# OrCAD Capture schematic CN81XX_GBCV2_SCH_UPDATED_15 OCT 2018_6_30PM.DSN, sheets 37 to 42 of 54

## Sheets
37 41.TIVA IO'S: size Custom; title: TIVA IO'S
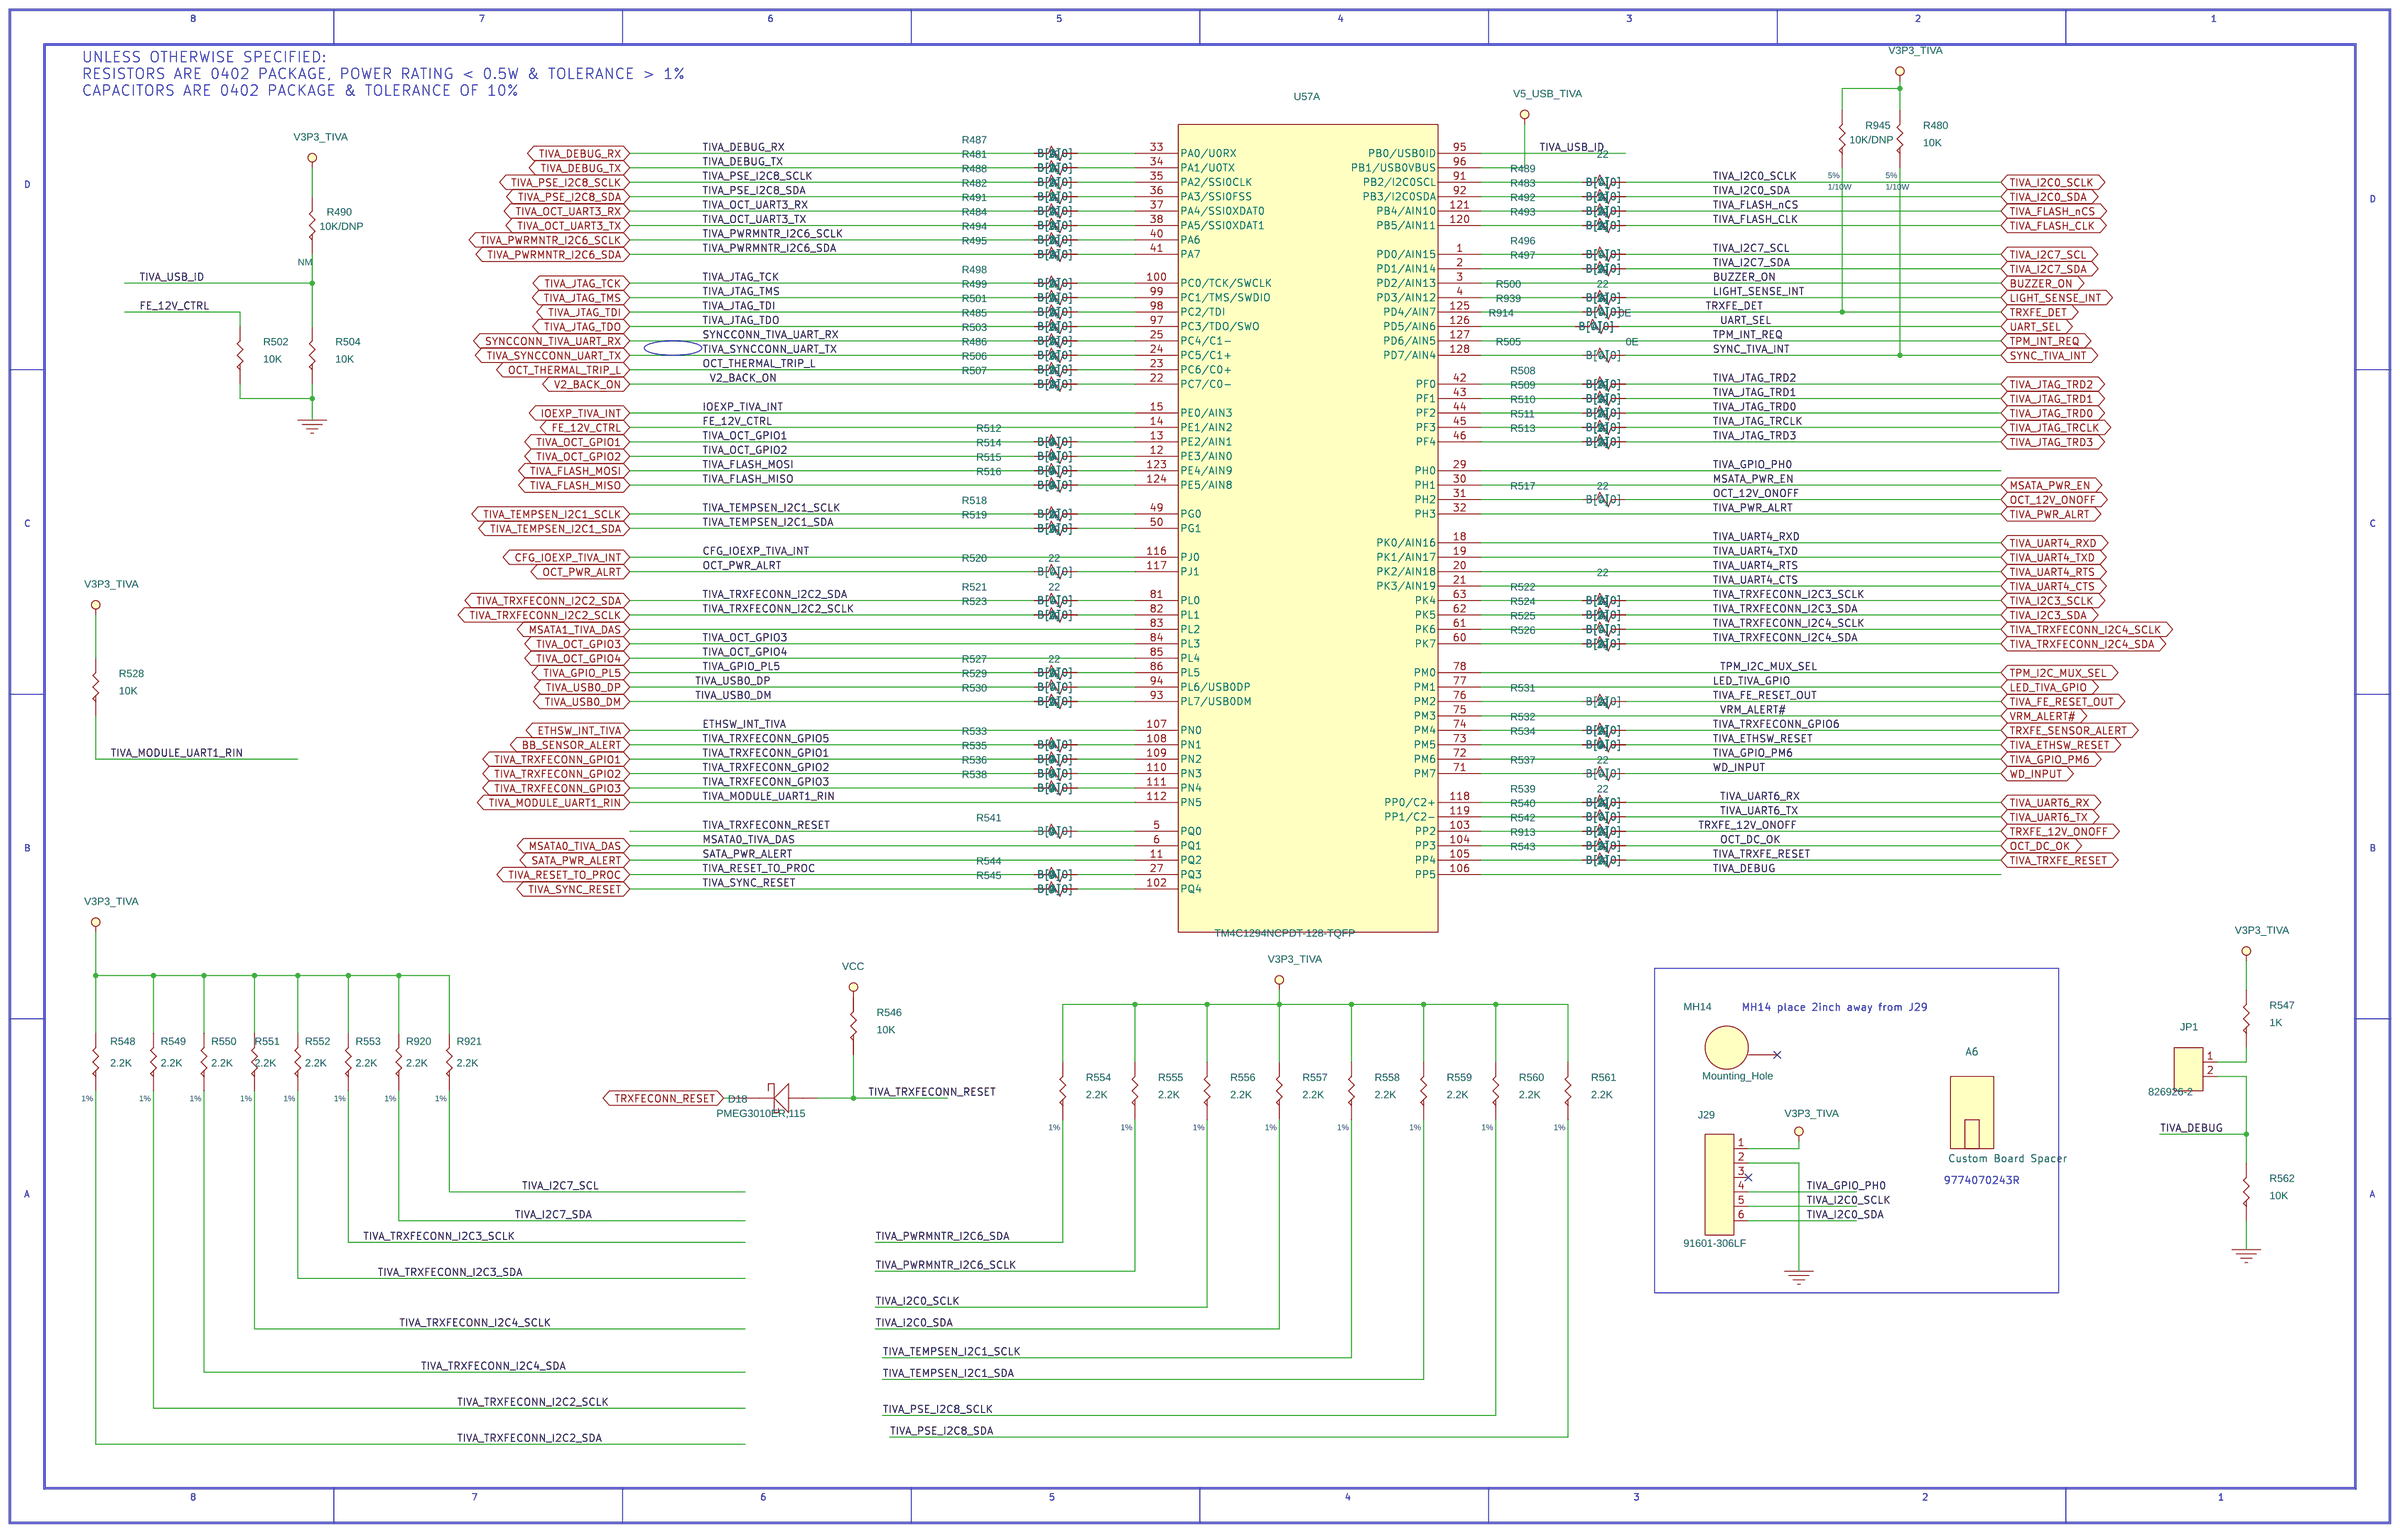
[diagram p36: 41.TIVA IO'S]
38 42.TIVA POWER: size Custom; title: TIVA POWER
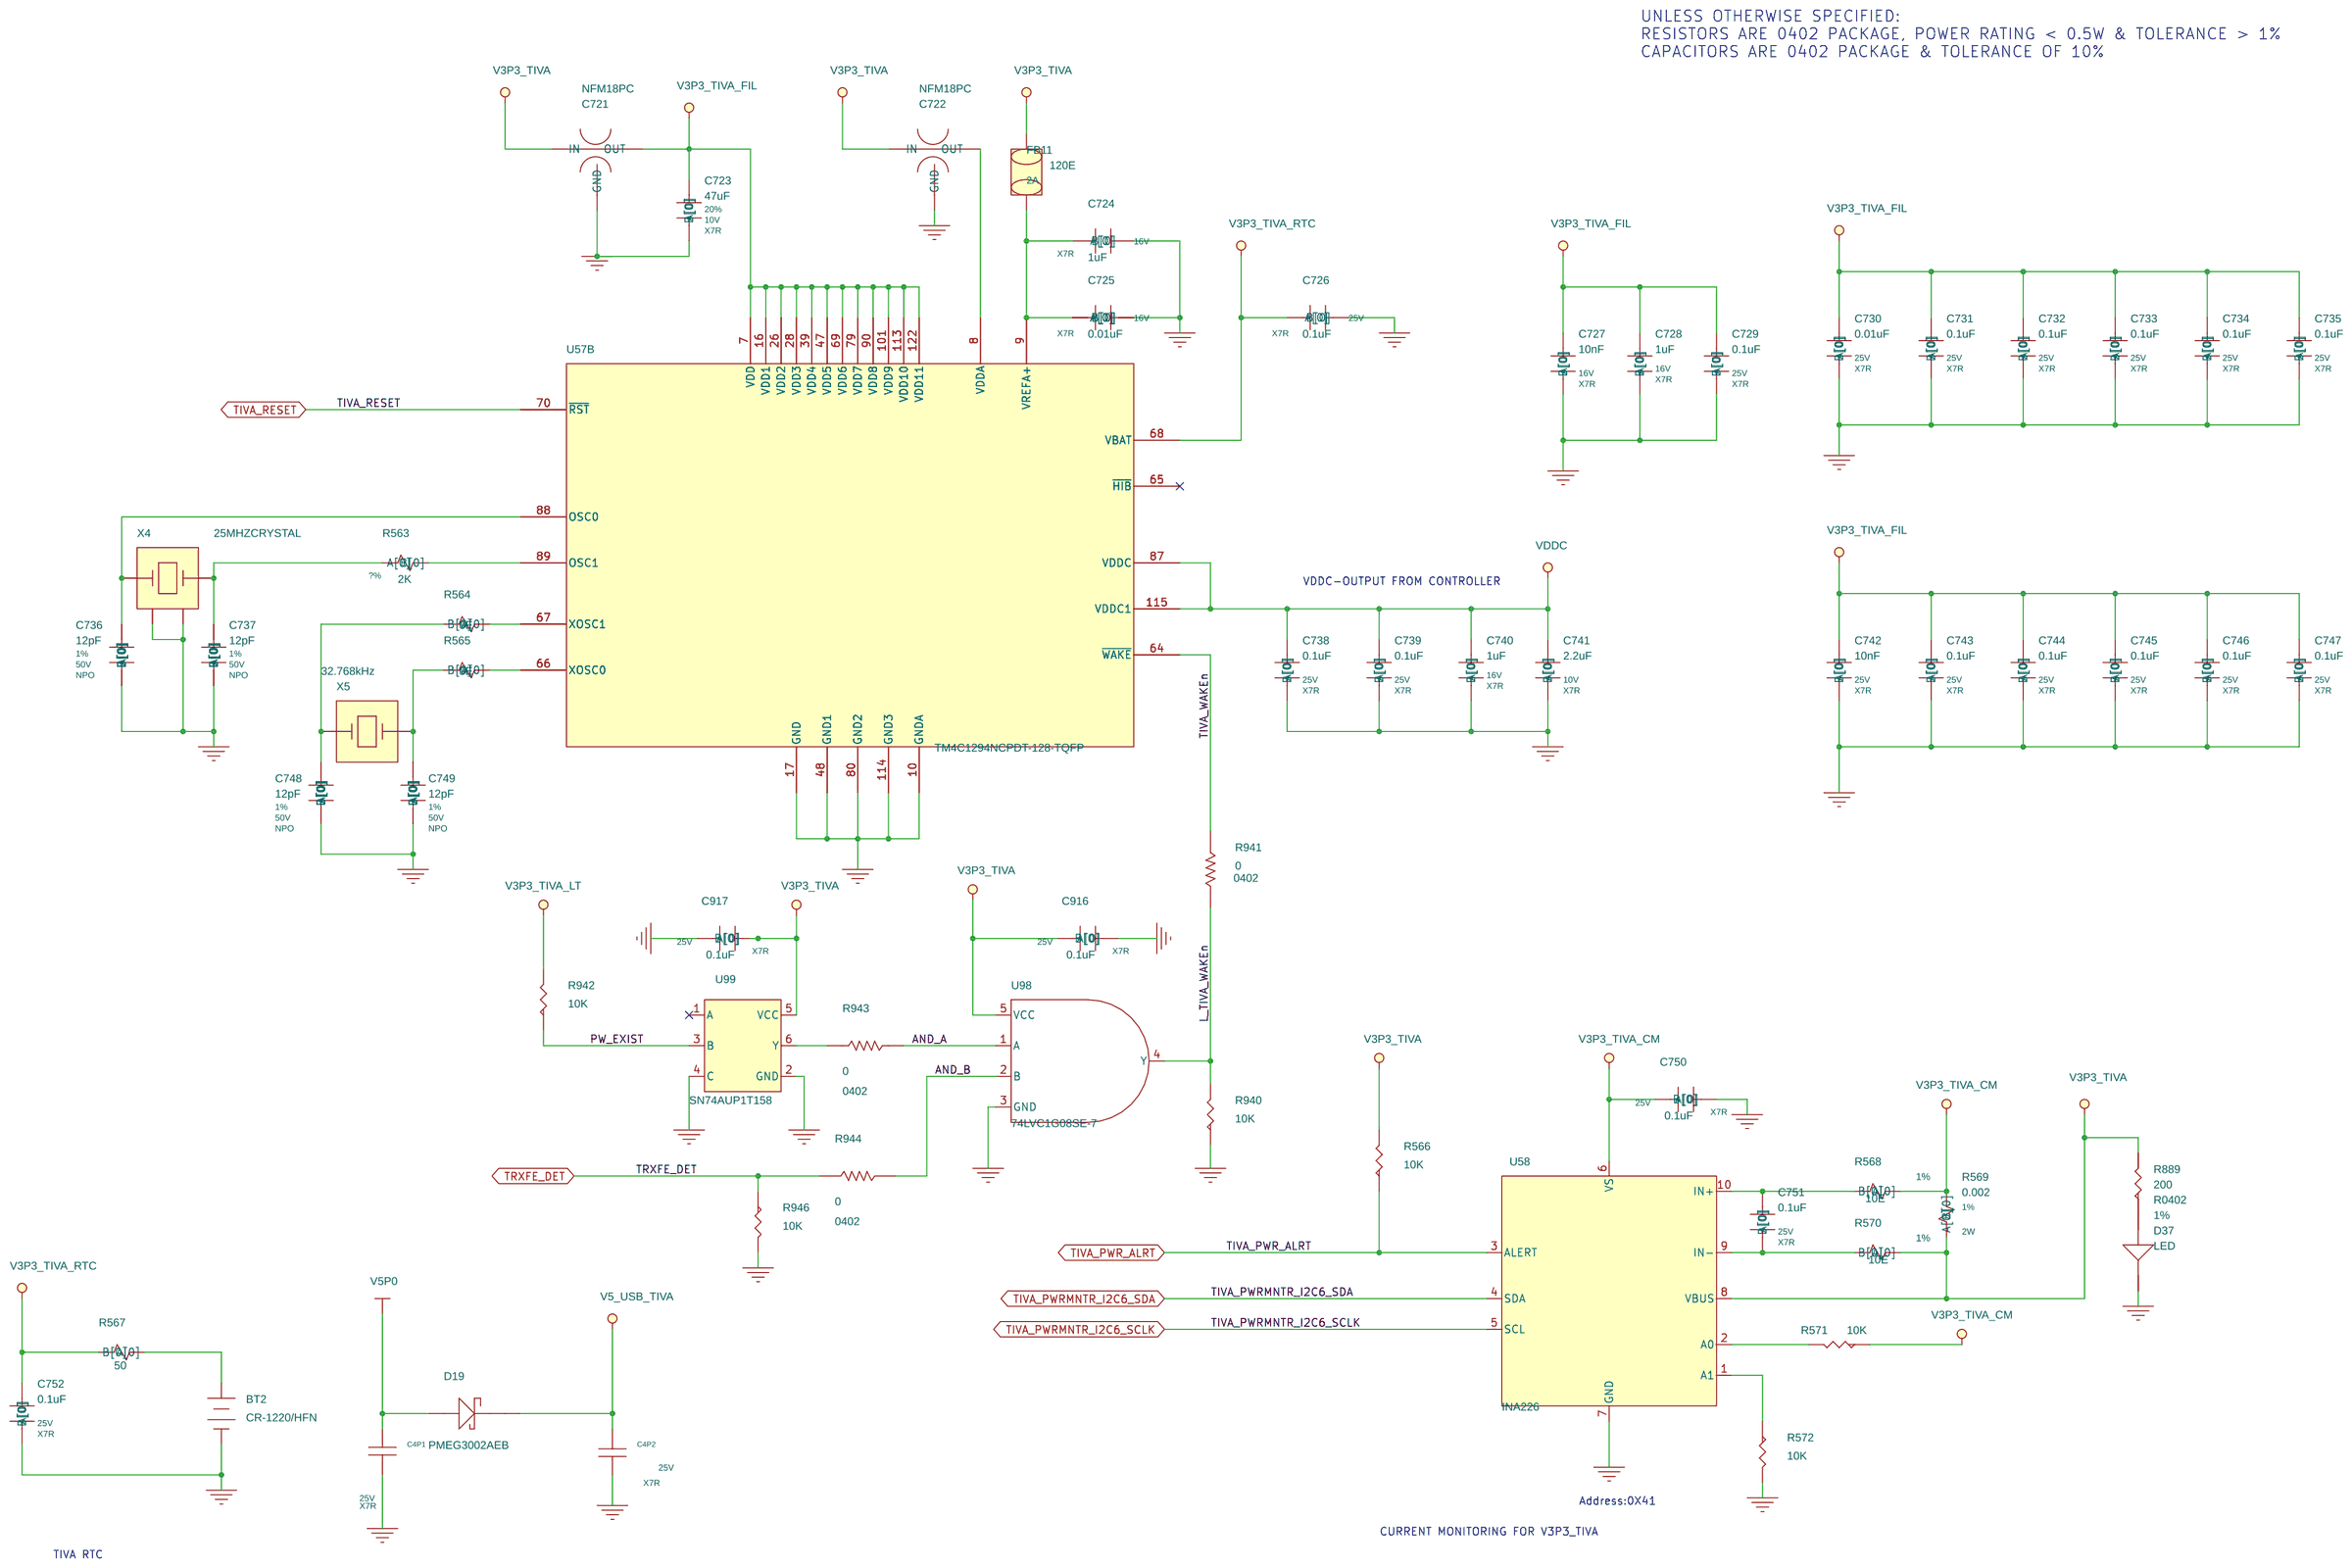
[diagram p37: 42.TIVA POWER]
39 43.TIVA JTAG CONNECTOR&ICD&LED: size B; title: TIVA JTAG CONNECTOR
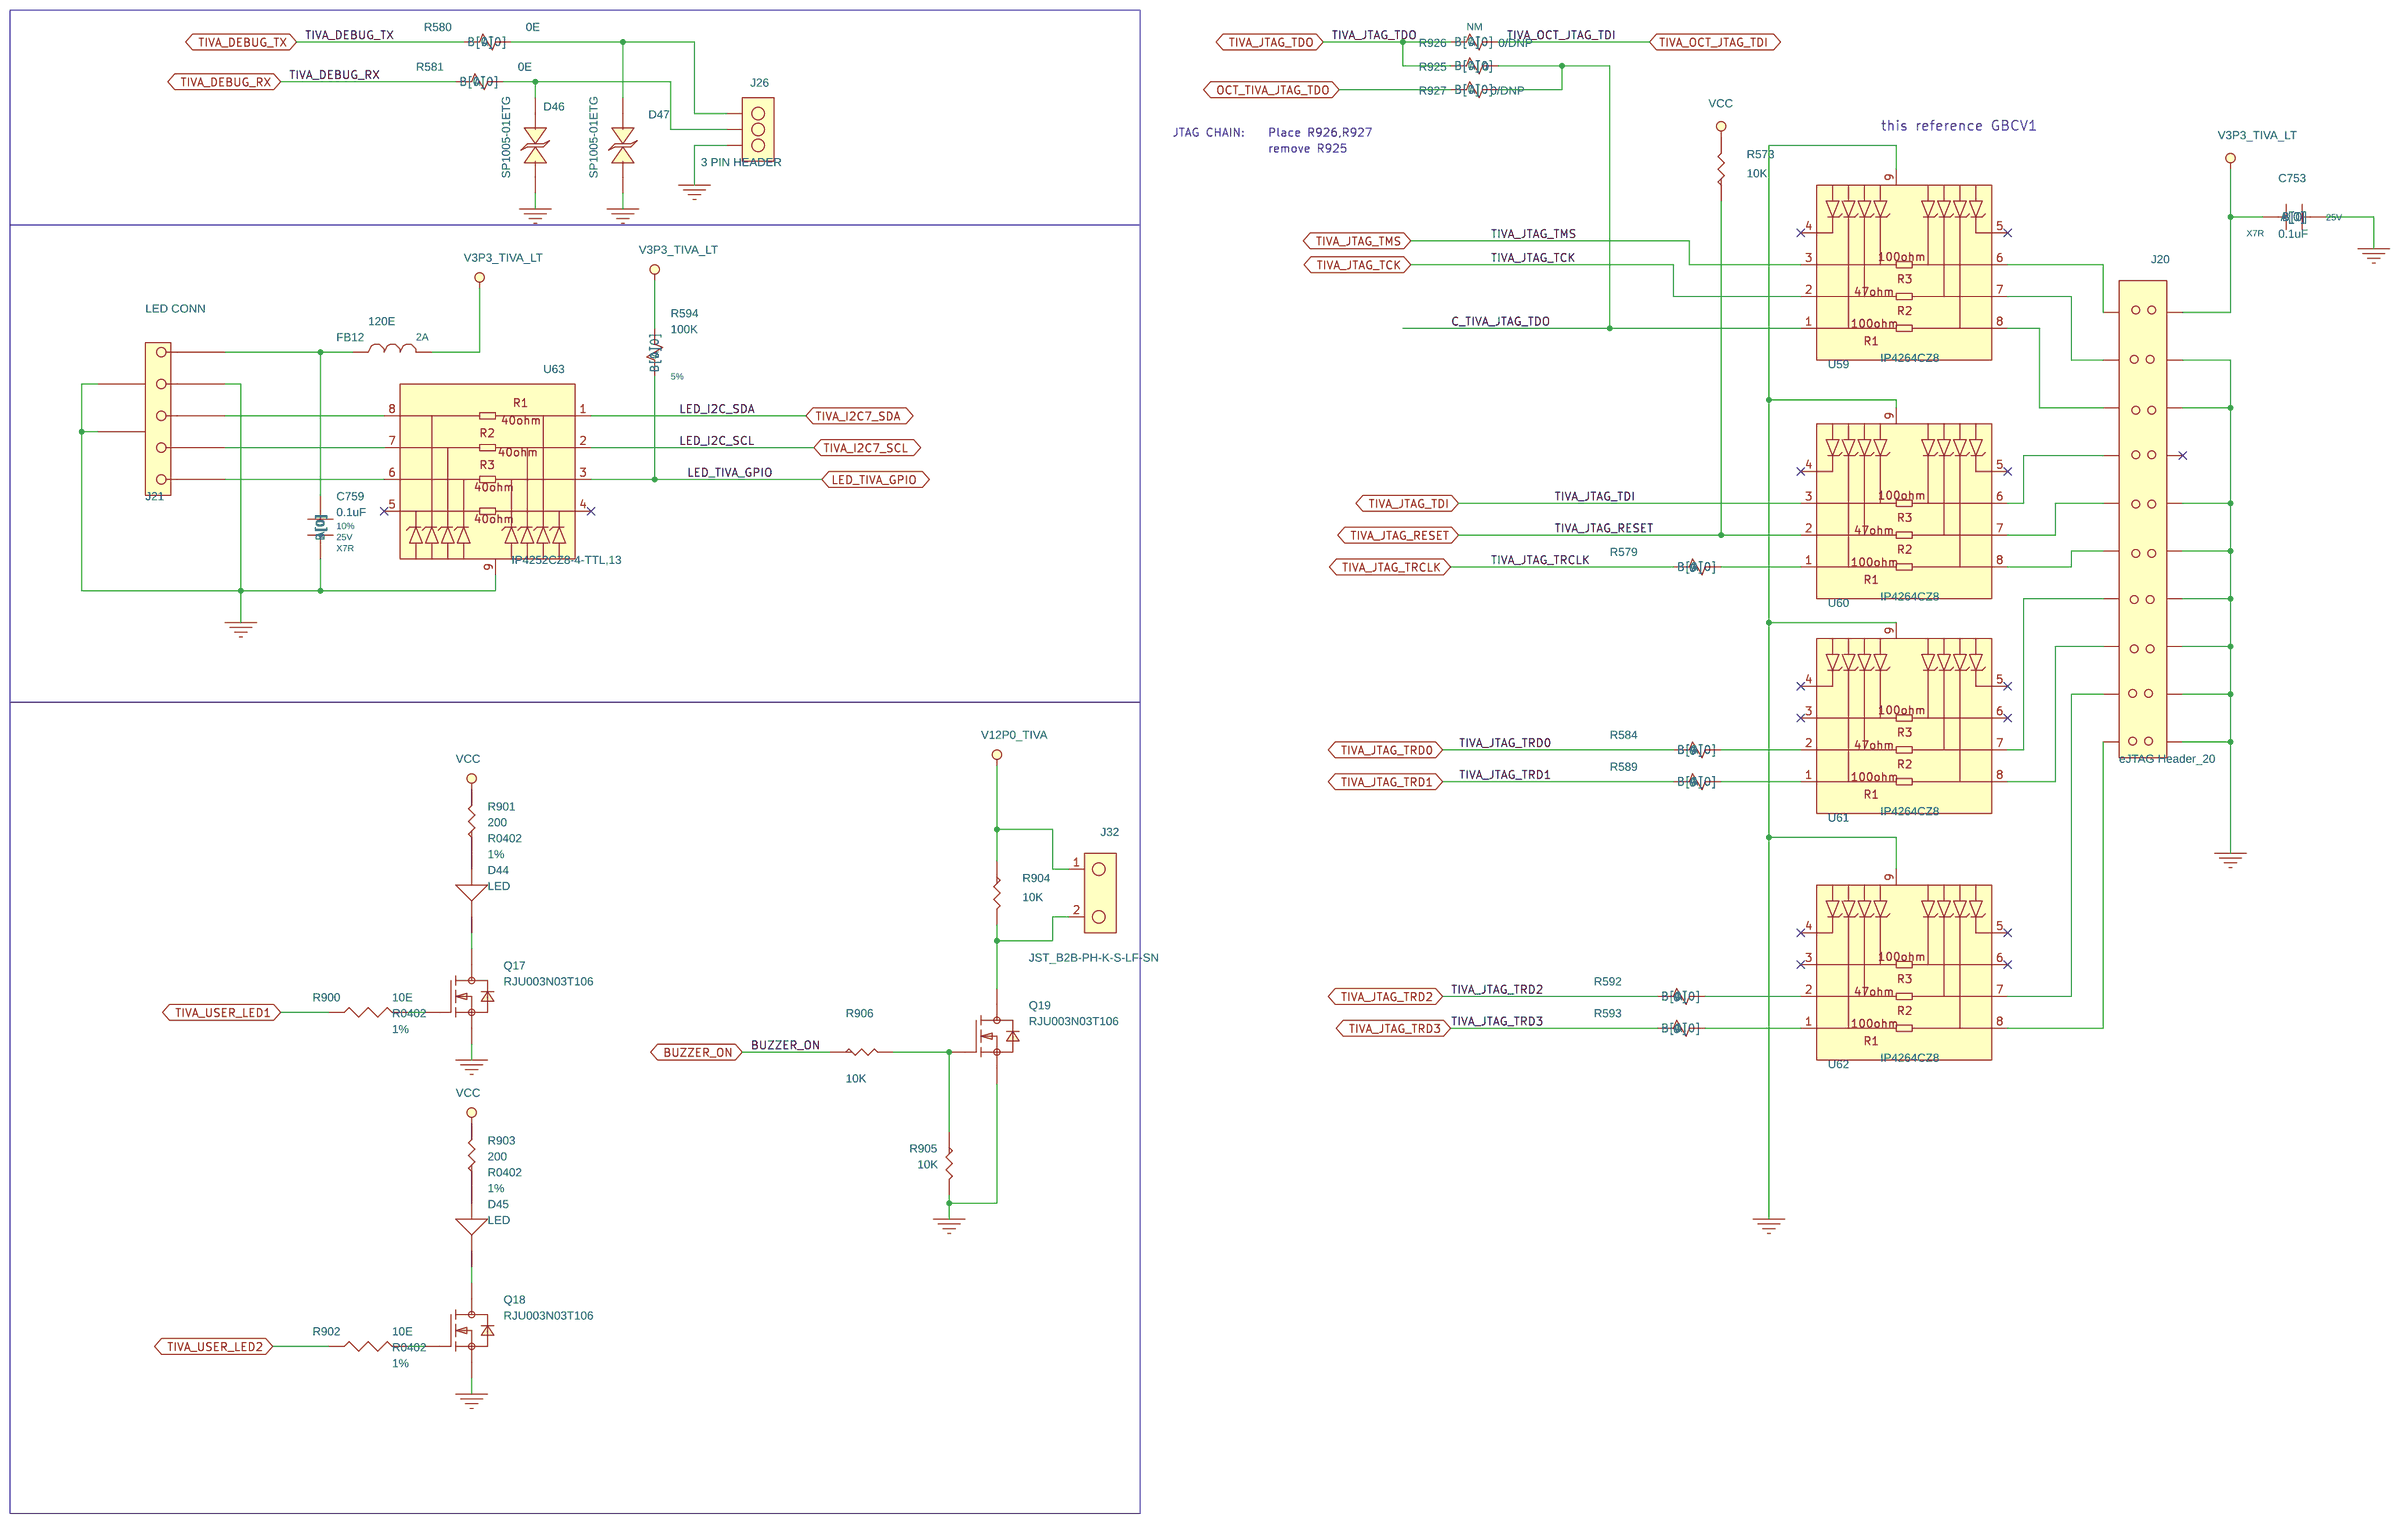
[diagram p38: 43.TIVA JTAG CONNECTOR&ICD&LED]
40 44.TIVA FLASH  & RESET: size Custom; title: TIVA FLASH & RESET
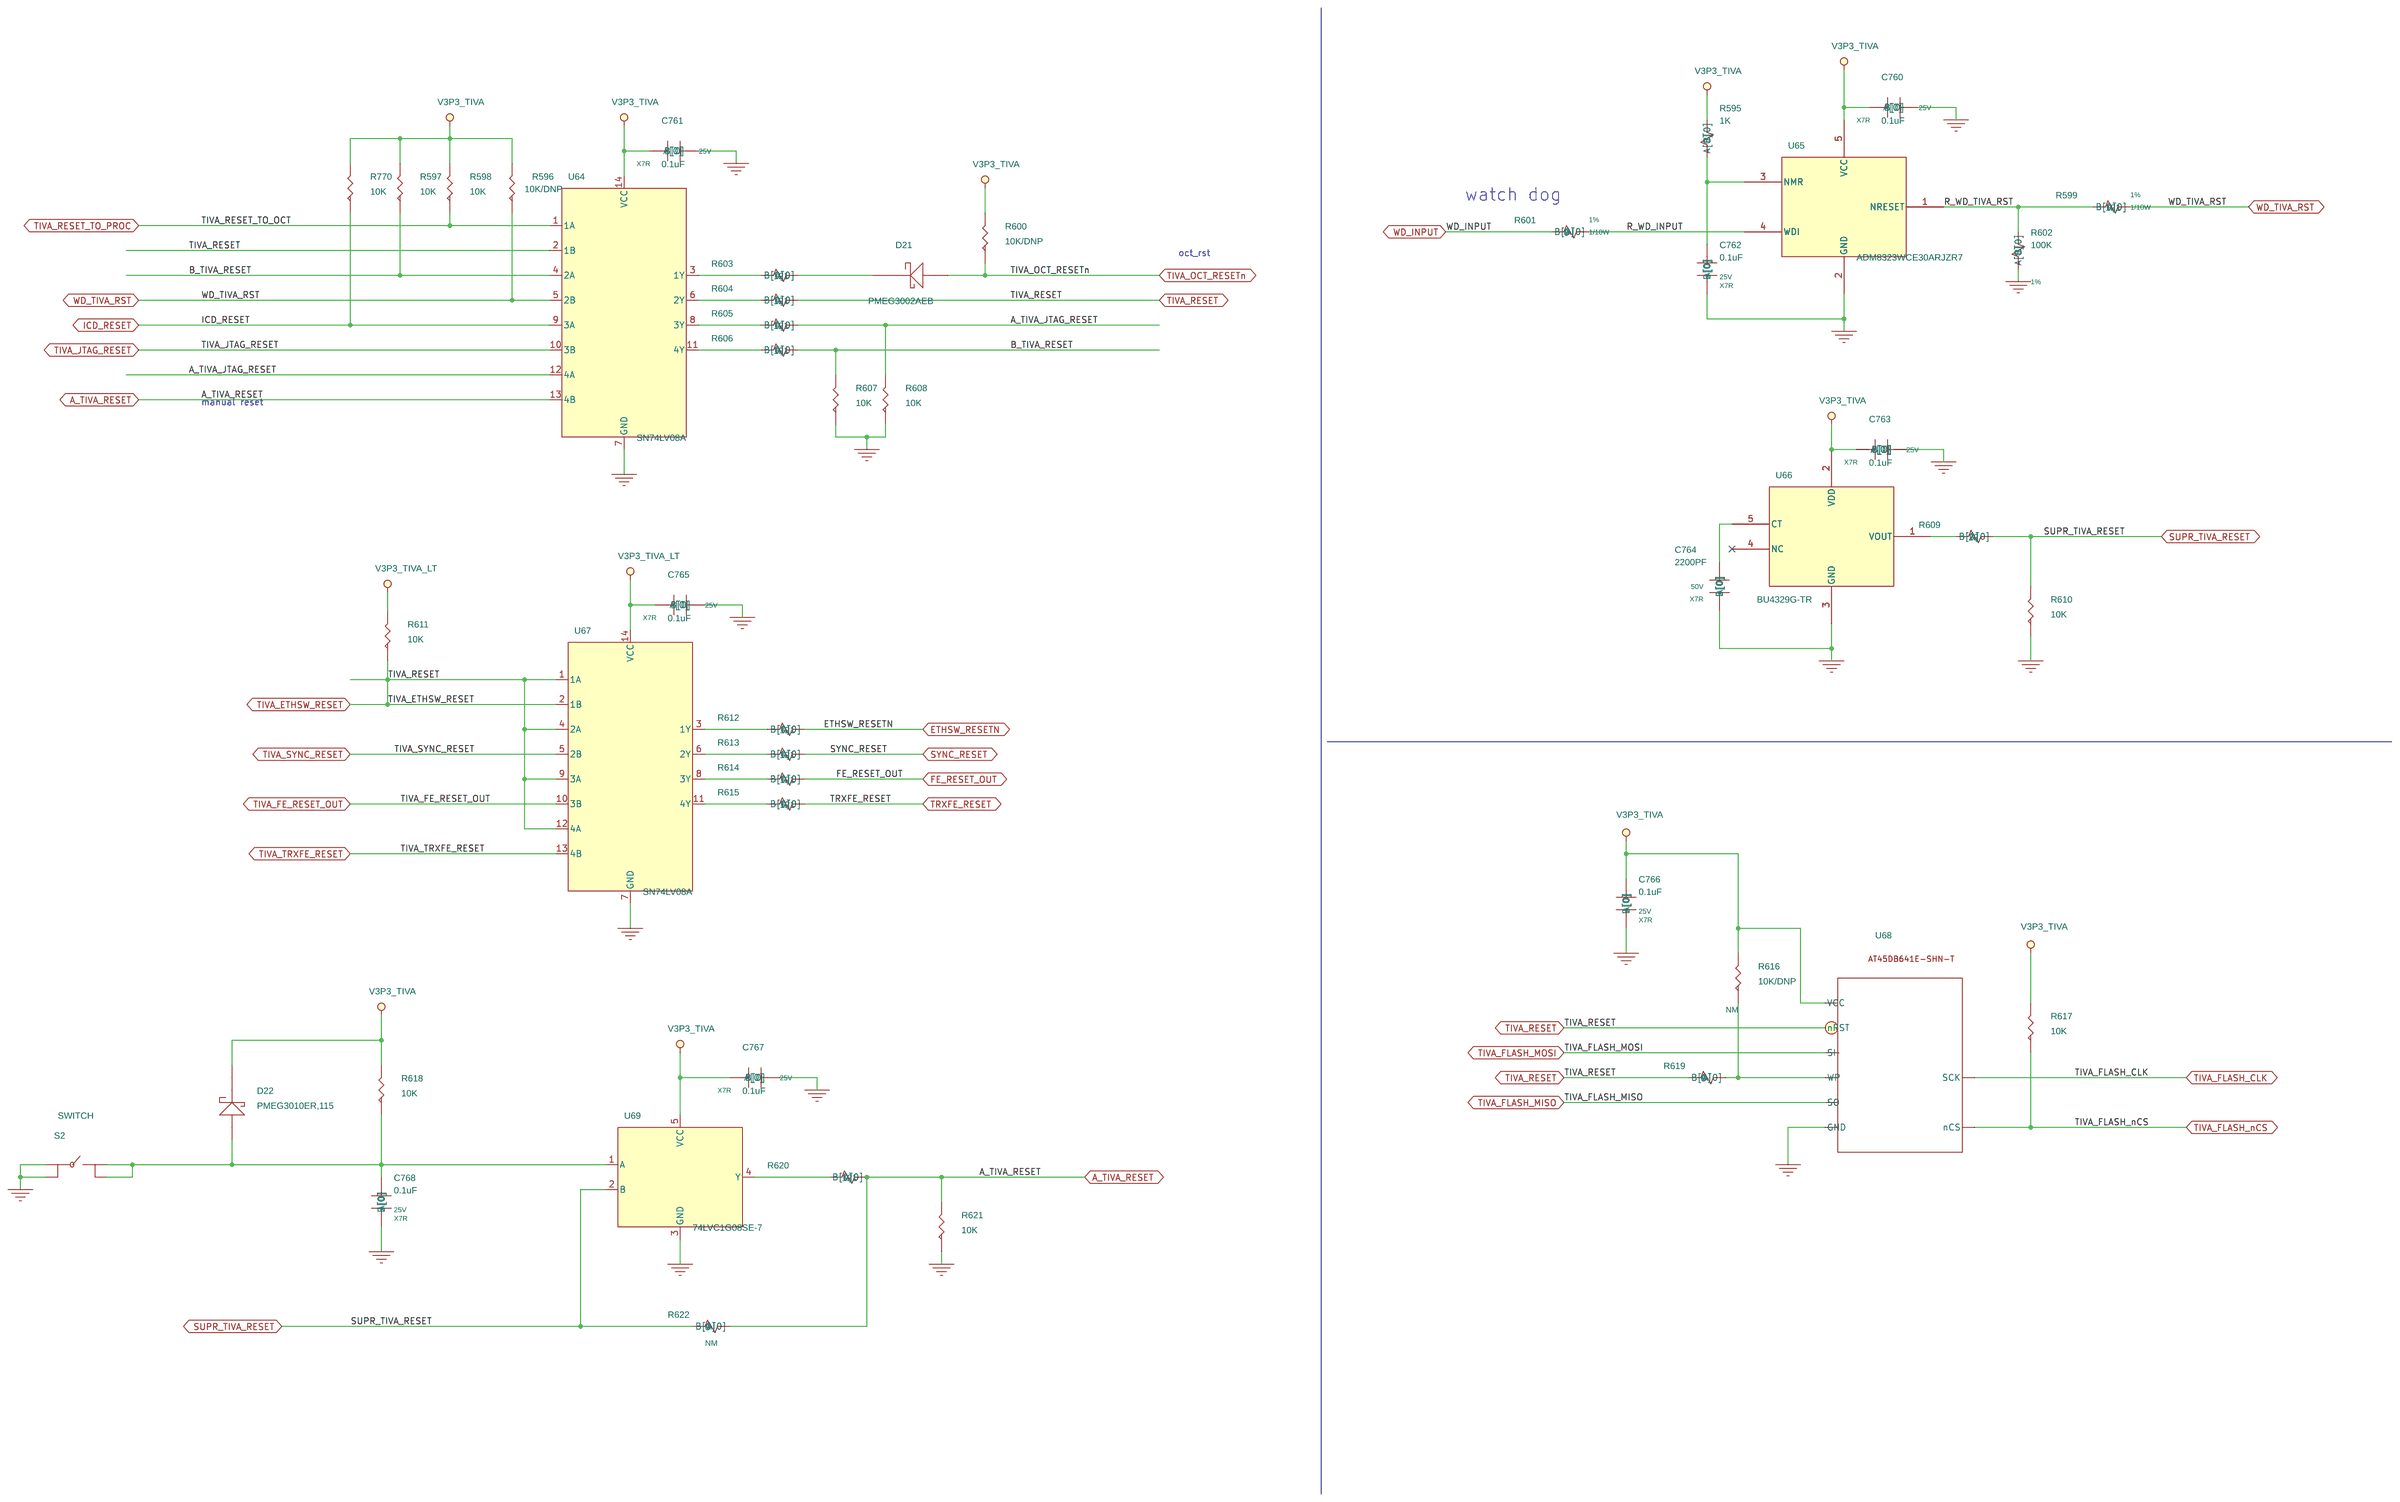
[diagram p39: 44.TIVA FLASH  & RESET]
41 45.TIVA EEPROM: size A; title: TIVA EEPROM
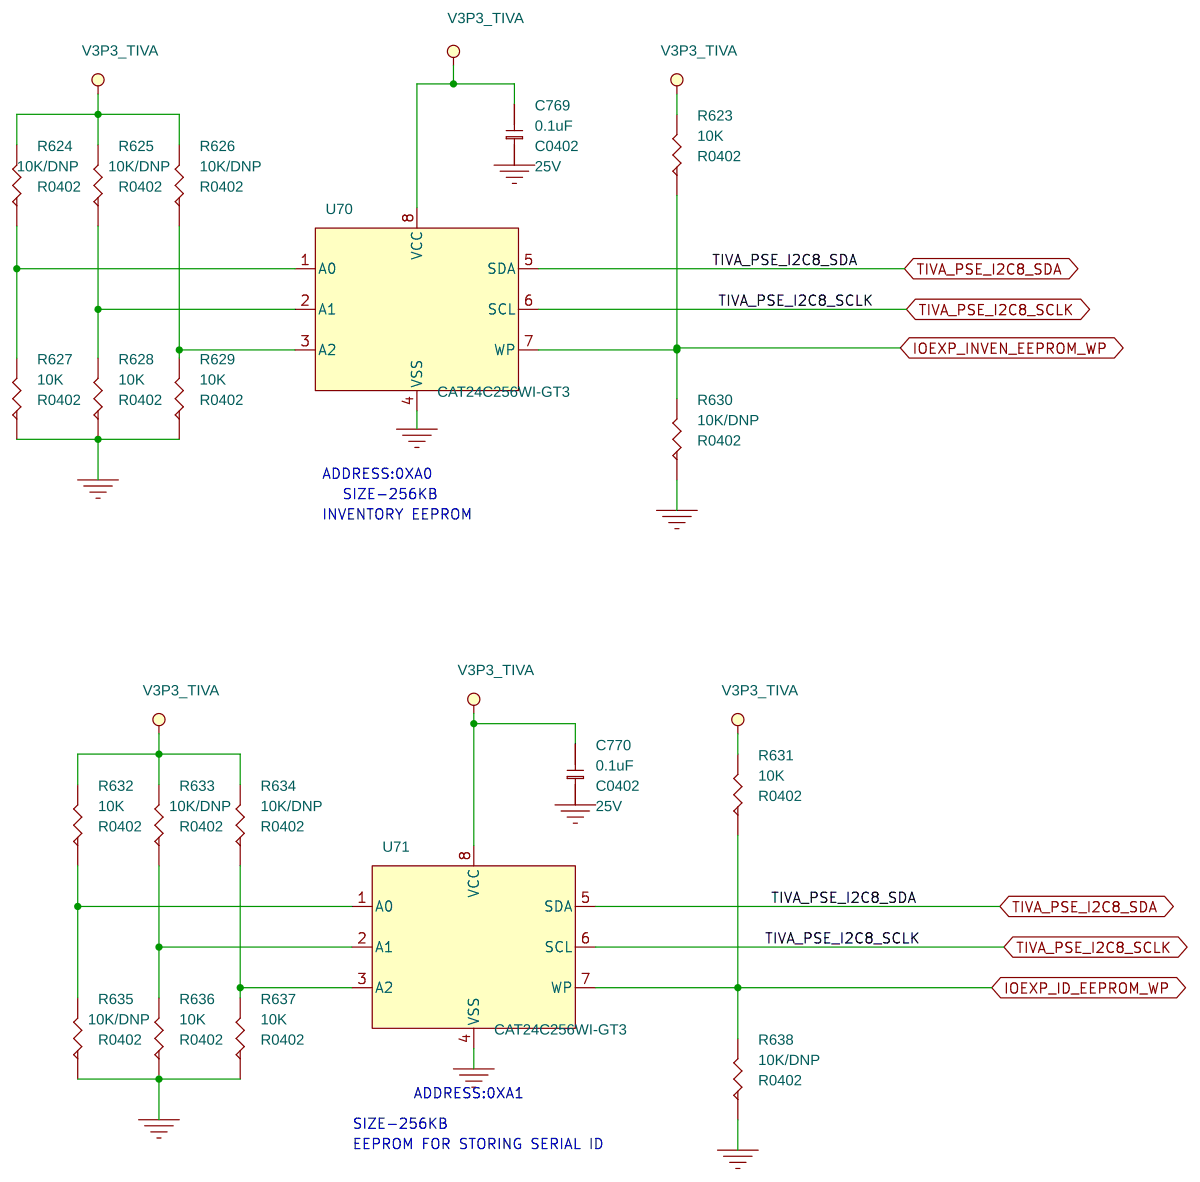
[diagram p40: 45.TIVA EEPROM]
42 46.BOARD TO BOARD CONNECTOR: size C; title: BOARD TO BOARD CONNECTOR
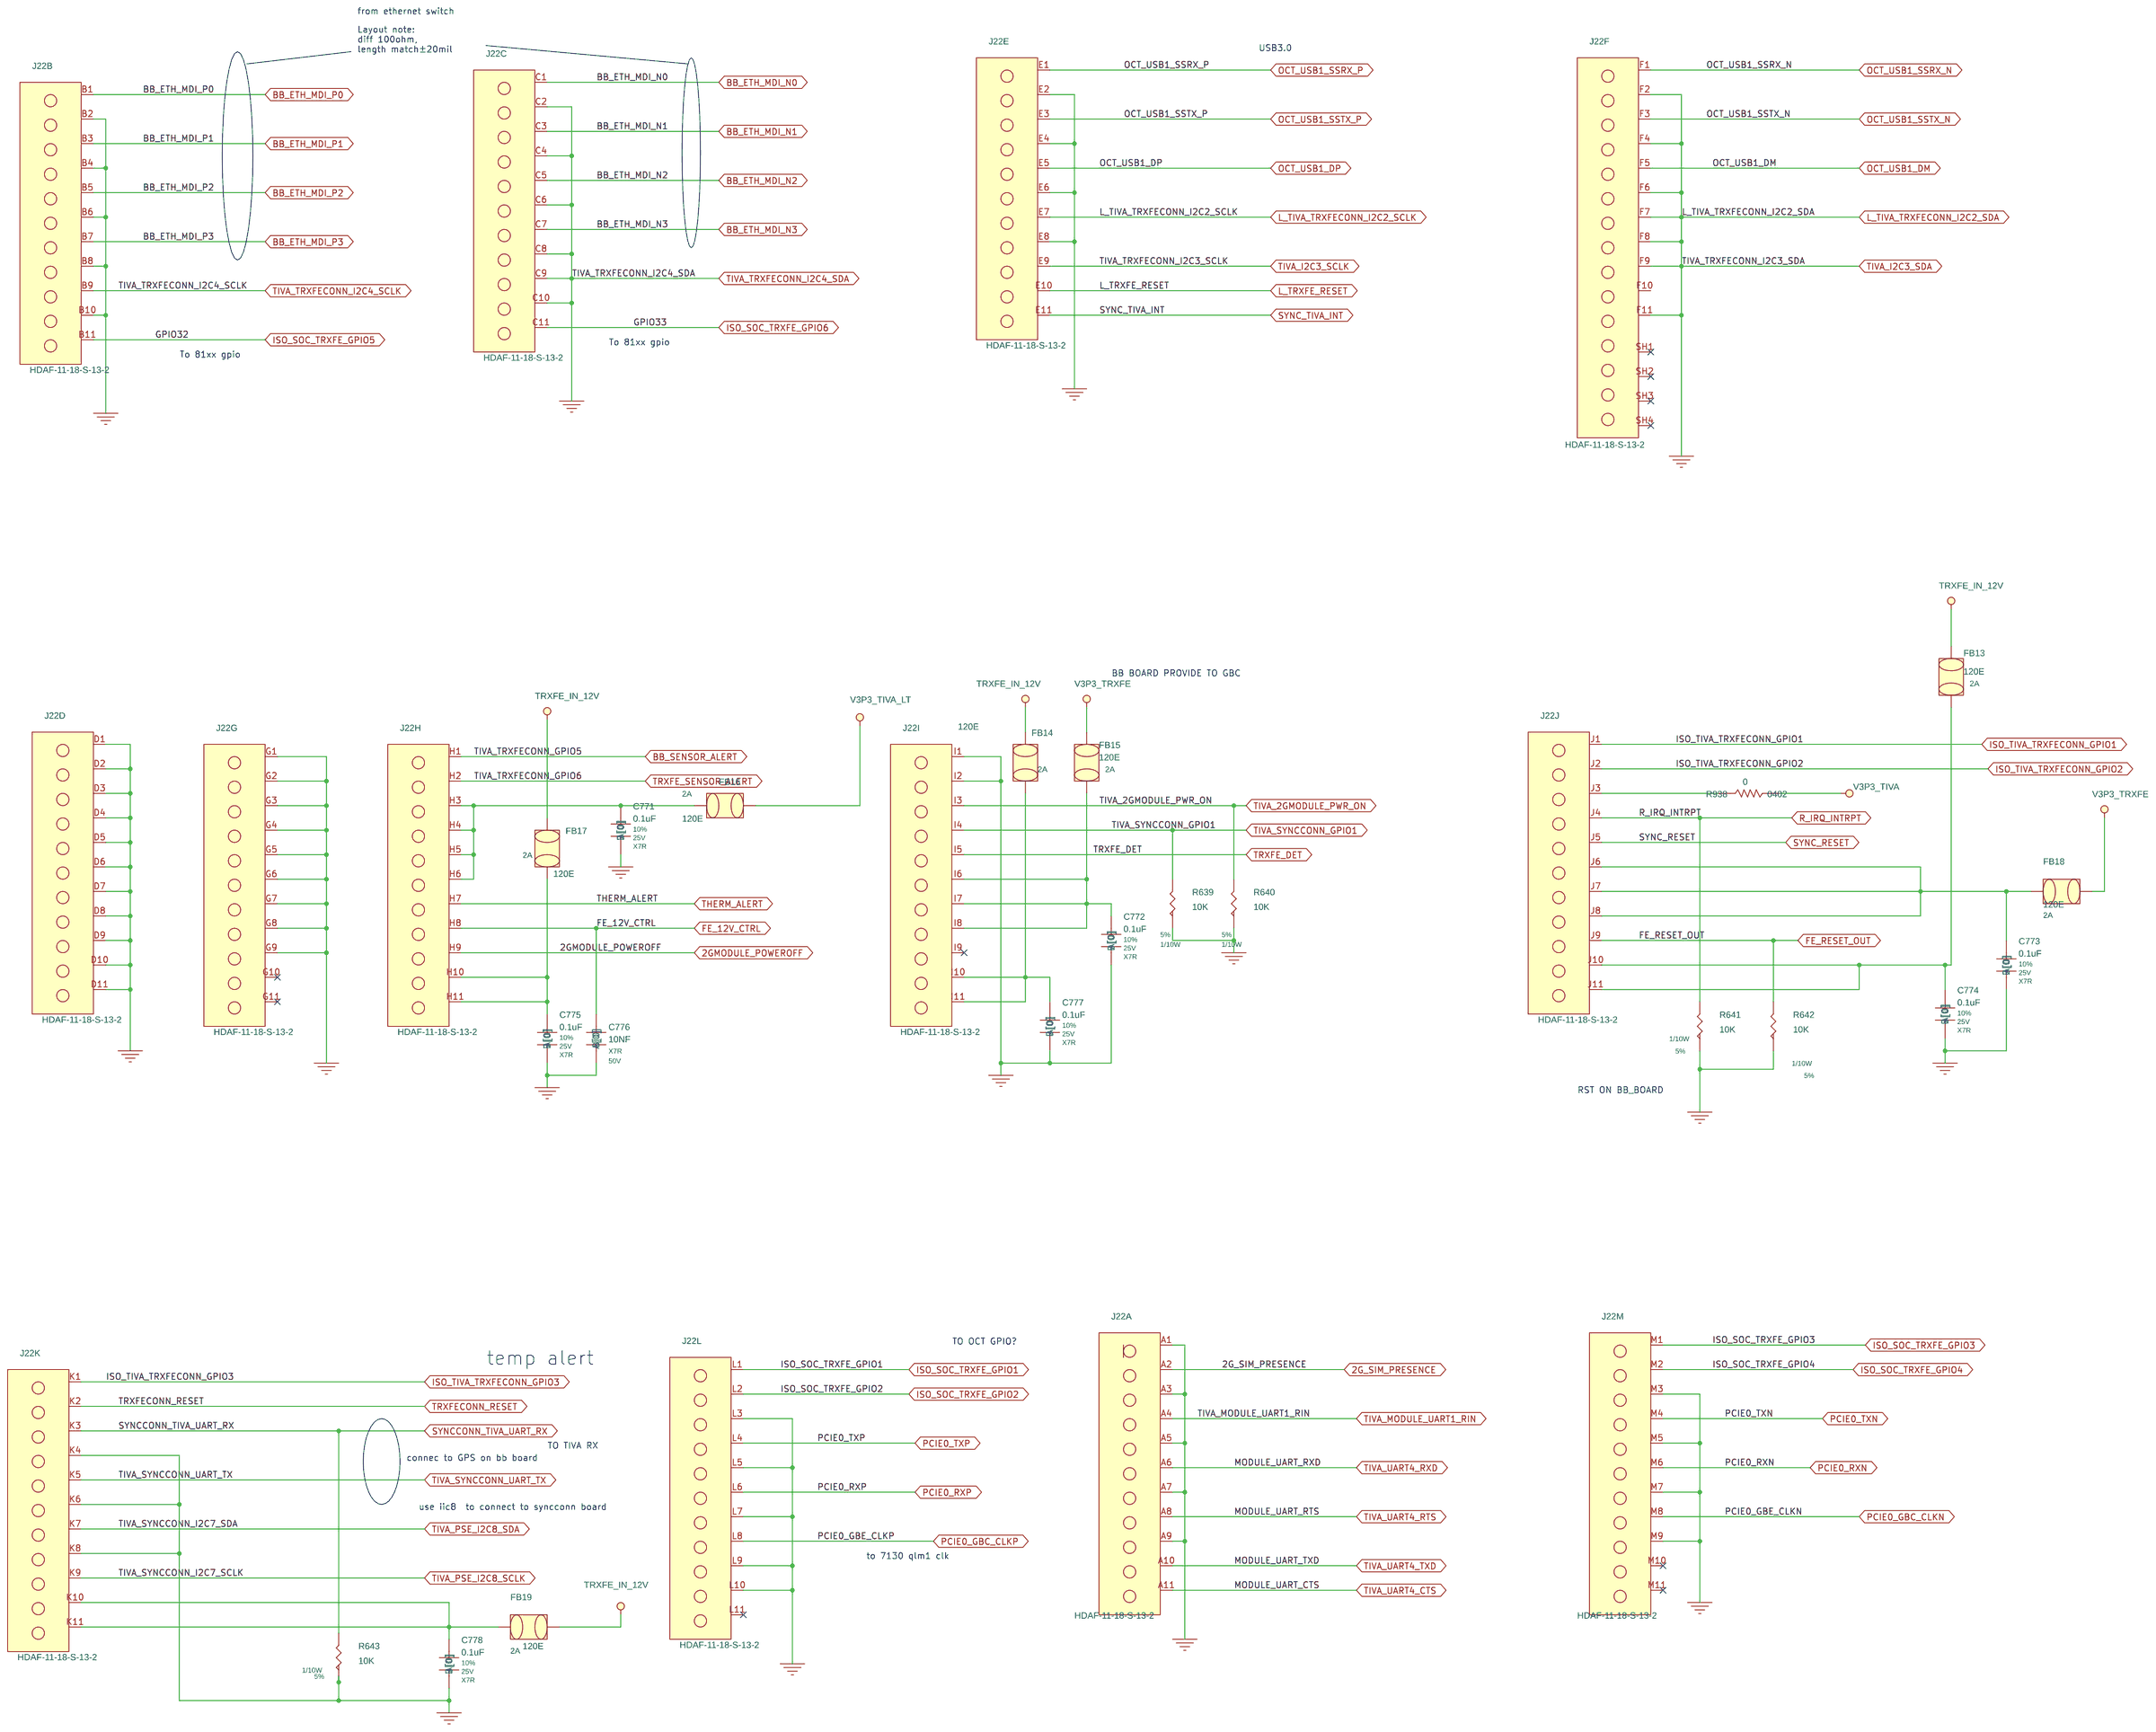
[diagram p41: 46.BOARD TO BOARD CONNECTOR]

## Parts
sheet 41.TIVA IO'S
A6  Custom Board Spacer  [9774030243R]
D18  PMEG3010ER,115  [SODFL3517X110N_NXP_AEE]
J29  91601-306LF  [91601-306LF]
JP1  826926-2  [SAMTEC_TSW-102-07-T-S]
MH14  Mounting_Hole  [SMD-5MM]
R480  10K  [R0402]
R481  22  [R0402]
R482  22  [R0402]
R483  22  [R0402]
R484  22  [R0402]
R485  22  [R0402]
R486  22  [R0402]
R487  22  [R0402]
R488  22  [R0402]
R489  22  [R0402]
R490  10K/DNP  [R0402]
R491  22  [R0402]
R492  22  [R0402]
R493  22  [R0402]
R494  22  [R0402]
R495  22  [R0402]
R496  22  [R0402]
R497  22  [R0402]
R498  22  [R0402]
R499  22  [R0402]
R500  22  [R0402]
R501  22  [R0402]
R502  10K  [R0402]
R503  22  [R0402]
R504  10K  [R0402]
R505  0E  [R0402]
R506  22  [R0402]
R507  22  [R0402]
R508  22  [R0402]
R509  22  [R0402]
R510  22  [R0402]
R511  22  [R0402]
R512  0  [R0402]
R513  22  [R0402]
R514  0  [R0402]
R515  0  [R0402]
R516  0  [R0402]
R517  22  [R0402]
R518  22  [R0402]
R519  22  [R0402]
R520  22  [R0402]
R521  22  [R0402]
R522  22  [R0402]
R523  22  [R0402]
R524  22  [R0402]
R525  22  [R0402]
R526  22  [R0402]
R527  22  [R0402]
R528  10K  [R0402]
R529  22  [R0402]
R530  22  [R0402]
R531  22  [R0402]
R532  22  [R0402]
R533  0  [R0402]
R534  0  [R0402]
R535  0  [R0402]
R536  0  [R0402]
R537  22  [R0402]
R538  0  [R0402]
R539  22  [R0402]
R540  22  [R0402]
R541  0  [R0402]
R542  22  [R0402]
R543  22  [R0402]
R544  0  [R0402]
R545  0  [R0402]
R546  10K  [R0402]
R547  1K  [R0402]
R548  2.2K  [R0402]
R549  2.2K  [R0402]
R550  2.2K  [R0402]
R551  2.2K  [R0402]
R552  2.2K  [R0402]
R553  2.2K  [R0402]
R554  2.2K  [R0402]
R555  2.2K  [R0402]
R556  2.2K  [R0402]
R557  2.2K  [R0402]
R558  2.2K  [R0402]
R559  2.2K  [R0402]
R560  2.2K  [R0402]
R561  2.2K  [R0402]
R562  10K  [R0402]
R913  22  [R0402]
R914  0E  [R0402]
R920  2.2K  [R0402]
R921  2.2K  [R0402]
R939  22  [R0402]
R945  10K/DNP  [R0402]
sheet 42.TIVA POWER
BT2  CR-1220/HFN  [BAT_CR-1220HFN]
C4P1  0.1uF  [C0402]
C4P2  0.1uF  [C0402]
C721  NFM18PC  [EMIFIL_NFM18PC104R1C3D]
C722  NFM18PC  [EMIFIL_NFM18PC104R1C3D]
C723  47uF  [cc1210]
C724  1uF  [C0402]
C725  0.01uF  [C0402]
C726  0.1uF  [C0402]
C727  10nF  [C0402]
C728  1uF  [C0402]
C729  0.1uF  [C0402]
C730  0.01uF  [C0402]
C731  0.1uF  [C0402]
C732  0.1uF  [C0402]
C733  0.1uF  [C0402]
C734  0.1uF  [C0402]
C735  0.1uF  [C0402]
C736  12pF  [C0402]
C737  12pF  [C0402]
C738  0.1uF  [C0402]
C739  0.1uF  [C0402]
C740  1uF  [C0402]
C741  2.2uF  [C0402]
C742  10nF  [C0402]
C743  0.1uF  [C0402]
C744  0.1uF  [C0402]
C745  0.1uF  [C0402]
C746  0.1uF  [C0402]
C747  0.1uF  [C0402]
C748  12pF  [C0402]
C749  12pF  [C0402]
C750  0.1uF  [C0402]
C751  0.1uF  [C0402]
C752  0.1uF  [C0402]
C916  0.1uF  [C0402]
C917  0.1uF  [C0402]
D19  PMEG3002AEB  [SODFL1608X65N_AEE]
D37  LED  [LED_LTST-C190]
FB11  120E  [INDC1608X95M]
R563  2K  [R0402]
R564  0E  [R0402]
R565  0E  [R0402]
R566  10K  [R0402]
R567  50  [R0402]
R568  10E  [R0402]
R569  0.002  [R2512]
R570  10E  [R0402]
R571  10K  [R0402]
R572  10K  [R0402]
R889  200  [R0402]
R940  10K  [R0402]
R941  0  [R0402]
R942  10K  [R0402]
R943  0  [R0402]
R944  0  [R0402]
R946  10K  [R0402]
U57  TM4C1294NCPDT-128-TQFP  [QFP40P1600X1600X120-128N]  (sections A,B,C)
U58  INA226  [VSSOP50P490X110-10N]
U98  74LVC1G08SE-7  [SC70_5P]
U99  SN74AUP1T158  [SC70_6P]
X4  25MHZCRYSTAL  [SMY_FA128]
X5  32.768kHz  [XTAL205X120X60N]
sheet 43.TIVA JTAG CONNECTOR&ICD&LED
C753  0.1uF  [C0402]
C759  0.1uF  [C0402]
D44  LED  [LED_LTST-C190]
D45  LED  [LED_LTST-C190]
D46  SP1005-01ETG  [SOD882]
D47  SP1005-01ETG  [SOD882]
FB12  120E  [INDC1608X95M]
J20  eJTAG Header_20  [M50-3601042]
J21  LED CONN  [JST_B5B-PH-SM4-TB]
J26  3 PIN HEADER  [HDR_1X3]
J32  JST_B2B-PH-K-S-LF-SN  [JST_B2B-PH-K-S-LF-SN]
Q17  RJU003N03  [UMT3]
Q18  RJU003N03  [UMT3]
Q19  RJU003N03  [UMT3]
R573  10K  [R0402]
R579  0  [R0402]
R580  0E  [R0402]
R581  0E  [R0402]
R584  0  [R0402]
R589  0  [R0402]
R592  0  [R0402]
R593  0  [R0402]
R594  100K  [R0402]
R900  10E  [R0402]
R901  200  [R0402]
R902  10E  [R0402]
R903  200  [R0402]
R904  10K  [R0402]
R905  10K  [R0402]
R906  10K  [R0402]
R925  0  [R0402]
R926  0/DNP  [R0402]
R927  0/DNP  [R0402]
U59  IP4264CZ8  [SON40P135X170X55-9N]
U60  IP4264CZ8  [SON40P135X170X55-9N]
U61  IP4264CZ8  [SON40P135X170X55-9N]
U62  IP4264CZ8  [SON40P135X170X55-9N]
U63  IP4252CZ8-4-TTL,13  [SON40P135X170X55-9N]
sheet 44.TIVA FLASH  & RESET
C760  0.1uF  [C0402]
C761  0.1uF  [C0402]
C762  0.1uF  [C0402]
C763  0.1uF  [C0402]
C764  2200PF  [C0402]
C765  0.1uF  [C0402]
C766  0.1uF  [C0402]
C767  0.1uF  [C0402]
C768  0.1uF  [C0402]
D21  PMEG3002AEB  [SODFL1608X65N_AEE]
D22  PMEG3010ER,115  [SODFL3517X110N_NXP_AEE]
R595  1K  [R0402]
R596  10K/DNP  [R0402]
R597  10K  [R0402]
R598  10K  [R0402]
R599  121  [R0402]
R600  10K/DNP  [R0402]
R601  0  [R0402]
R602  100K  [R0402]
R603  121  [R0402]
R604  121  [R0402]
R605  121  [R0402]
R606  121  [R0402]
R607  10K  [R0402]
R608  10K  [R0402]
R609  22  [R0402]
R610  10K  [R0402]
R611  10K  [R0402]
R612  121  [R0402]
R613  121  [R0402]
R614  121  [R0402]
R615  121  [R0402]
R616  10K/DNP  [R0402]
R617  10K  [R0402]
R618  10K  [R0402]
R619  0  [R0402]
R620  121  [R0402]
R621  10K  [R0402]
R622  0  [R0402]
R770  10K  [R0402]
S2  SWITCH  [SW_B3SL-1022P]
U64  SN74LV08A  [TSSOP65P640X120-14N]
U65  ADM8323WCE30ARJZR7  [SOT95P280X145-5N_AD]
U66  BU4329G-TR  [SSOP95P280X125-5N]
U67  SN74LV08A  [TSSOP65P640X120-14N]
U68  AT45DB641E-SHN-T  [SOIC127P798X216-8N]
U69  74LVC1G08SE-7  [SC70_5P]
sheet 45.TIVA EEPROM
C769  0.1uF  [C0402]
C770  0.1uF  [C0402]
R623  10K  [R0402]
R624  10K/DNP  [R0402]
R625  10K/DNP  [R0402]
R626  10K/DNP  [R0402]
R627  10K  [R0402]
R628  10K  [R0402]
R629  10K  [R0402]
R630  10K/DNP  [R0402]
R631  10K  [R0402]
R632  10K  [R0402]
R633  10K/DNP  [R0402]
R634  10K/DNP  [R0402]
R635  10K/DNP  [R0402]
R636  10K  [R0402]
R637  10K  [R0402]
R638  10K/DNP  [R0402]
U70  CAT24C256WI-GT3  [SOIC127P600X175-8N_ON-SEMI]
U71  CAT24C256WI-GT3  [SOIC127P600X175-8N_ON-SEMI]
sheet 46.BOARD TO BOARD CONNECTOR
C771  0.1uF  [C0402]
C772  0.1uF  [C0402]
C773  0.1uF  [C0402]
C774  0.1uF  [C0402]
C775  0.1uF  [C0402]
C776  10NF  [C0402]
C777  0.1uF  [C0402]
C778  0.1uF  [C0402]
FB13  120E  [INDC1608X95M]
FB14  120E  [INDC1608X95M]
FB15  120E  [INDC1608X95M]
FB16  120E  [INDC1608X95M]
FB17  120E  [INDC1608X95M]
FB18  120E  [INDC1608X95M]
FB19  120E  [INDC1608X95M]
J22  HDAF-11-18-S-13-2  [SAMTEC_HDAF-11-18P0-S-13-2]  (sections A,B,C,D,E,F,G,H,I,J,K,L,M)
R639  10K  [R0402]
R640  10K  [R0402]
R641  10K  [R0402]
R642  10K  [R0402]
R643  10K  [R0402]
R938  0  [R0402]

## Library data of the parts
A6 = 4-881545-2: ROUND STANDOFF M2 STEEL 3MM; Manufacturer: Wurth Electronics Inc
D18 D22 = DIODE_SCHOTTKY_30V_0.2A_SOD523: DIODE SCHOTTKY 30V 1A SOD123W; Manufacturer Part Number: PMEG3002AEB,115
J29 = 91601-306LF
JP1 = Header_1X2: Manufacturer: Samtec; Part Number: TSW-102-07-T-S
MH14 = Mounting_Hole_0: Section: SG1000
R480 R502 R504 R528 R546 R562 R566 R571-R573 R597 R598 R600 R607 R608 R610 R611 R617 R618 R621 R639-R643 R770 R940 R942 R945 R946 = RESISTOR_2: RES 10K OHM 1/10W 5% 0402 SMD; Manufacturer: Panasonic Electronic Components; Part Number: ERJ-2GEJ103X; TOLERANCE: 5%; WATTAGE: 1/10W
R481-R489 R491-R501 R503 R506-R511 R513 R517-R527 R529-R532 R537 R539 R540 R542 R543 R609 R913 R939 = RES_22_OHM_1_10W_5%_0402_SMD_0: RES SMD 22 OHM 1% 1/10W 0402; Manufacturer: VISHAY DALE; Manufacturer Part Number: CRCW040222R0FKED; Part Number: ERJ-2RKF22R0X; TOLERANCE: 1%; WATTAGE: 1/10W
R490 R596 R616 = RESISTOR_2: RES 10K OHM 1/10W 5% 0402 SMD; Manufacturer: Panasonic Electronic Components; No_Mount: NM; Part Number: ERJ-2GEJ103X; TOLERANCE: 5%; WATTAGE: 1/10W
R505 R512 R514-R516 R533-R536 R538 R541 R544 R545 R564 R565 R580 R581 R619 R914 = RES_1.0_OHM_1_16W_0402_SMD: RES SMD 0.0OHM JUMPER 1/16W 0402; MATERIAL: ?; Manufacturer: VISHAY DALE; Manufacturer Part Number: CRCW04020000Z0ED; Part Number: ERJ-2GE0R00X; TOLERANCE: ?; Wattage: 1/10W
R547 = RESISTOR_2: RES SMD 1K OHM 5% 1/16W 0402; Manufacturer: VISHAY DALE; Manufacturer Part Number: CRCW04021K00JNED; Part Number: ERJ-2GEJ102X; TOLERANCE: 5%; WATTAGE: 1/10W
R548-R561 R920 R921 = RESISTOR_2: RES SMD 2.2K OHM 1% 1/10W 0402; Manufacturer: Panasonic Electronic Components; Manufacturer Part Number: ERJ-2RKF2201X; Part Number: ERJ-2RKF2201X; TOLERANCE: 1%; WATTAGE: 1/10W
BT2 = BATTERY: BATTERY LITHIUM 3V COIN 16MM; ICA_MFR_NAME: PANASONIC CORP; ICA_PARTNUM: $$1651322$$CR1220; Manufacturer: Panasonic - BSG; Manufacturer Part Number: BR-1632/V1AN; Part Number: BR-1632/V1AN
C4P1 = cap_0402_0.1uF_16V_10%_X7R: CAP CER 0.1UF 25V 10% X7R 0402; MATERIAL: X7R; MFG: TAIYO; MFG_PN: TMK105BJ104KV-F; Manufacturer: MURATA; Manufacturer Part Number: GRM155R71C104KA88D; PART_NUMBER: G41157-001; PATH: I459; PHYS_PAGE: 24; Part Number: C1005X7R1E104K050BB; TOLERANCE: 10%; VOLTAGE: 25V; XY: (-7325,6525)
C4P2 = cap_0402_0.1uF_16V_10%_X7R: CAP CER 0.1UF 25V 10% X7R 0402; MATERIAL: X7R; MFG: TAIYO; MFG_PN: TMK105BJ104KV-F; Manufacturer: MURATA; Manufacturer Part Number: GRM155R71C104KA88D; PART_NUMBER: G41157-001; PATH: I462; PHYS_PAGE: 24; Part Number: C1005X7R1E104K050BB; TOLERANCE: 10%; VOLTAGE: 25V; XY: (-5175,6625)
C721 C722 = NFM18PC_0: FILTER LC HIGH FREQ 100000PF 0603; Manufacturer: Murata Electronics North America; Manufacturer Part Number: NFM18PC104R1C3D; No_Mount: Audio Codec; Part Number: NFM18PC104R1C3D
C723 = CAP_CER_0.1UF_10V_10%_X5R_0402: CAP CER 47UF 10V X7R 1210; MATERIAL: X7R; Manufacturer: Murata Electronics North America; PART_NUMBER: 0.1UF; Part Number: GRM32ER71A476ME15L; TOLERANCE: 20%; VOLTAGE: 10V
C724 C728 C740 = CAP-NP_1: CAP CER 1UF 16V 10% X7R 0603; MATERIAL: X7R; Manufacturer: Yageo; Part Number: CC0603KRX7R7BB105; TOLERANCE: 10%; VOLTAGE: 16V
C725 = CAP_CER_0.1UF_10V_10%_X5R_0402: CAP  0402 CER 0.01uF 16V 10%  X7R; MATERIAL: X7R; Manufacturer: Murata; Manufacturer Part Number: GRM155R71C103KA01J; PART_NUMBER: 0.1UF; Part Number: GRM155R71H103KA88D; TOLERANCE: 10%; VOLTAGE: 16V
C726 C729 C731-C735 C738 C739 C743-C747 C750-C753 C759-C763 C765-C768 C771-C775 C777 C778 C916 C917 = CAP_CER_0.1UF_10V_10%_X5R_0402: CAP CER 0.1UF 25V 10% X7R 0402; MATERIAL: X7R; Manufacturer: MURATA; Manufacturer Part Number: GRM155R71C104KA88D; PART_NUMBER: 0.1UF; Part Number: C1005X7R1E104K050BB; TOLERANCE: 10%; VOLTAGE: 25V
C727 = CAP-NP_1: CAP CER 10000PF 16V X7R 0402; MATERIAL: X7R; Manufacturer: Yageo; Part Number: CC0402KRX7R7BB103; TOLERANCE: 10%; VOLTAGE: 16V
C730 C742 = CAP-NP_1: CAP CER 10000PF 25V X7R 0402; MATERIAL: X7R; Manufacturer: Murata Electronics North America; Part Number: GRM155R71E103KA01D; TOLERANCE: 10%; VOLTAGE: 25V
C736 C737 C748 C749 = CAP-NP_1: CAP CER 12PF 50V NP0 0402; MATERIAL: NPO; Manufacturer: Kemet; Manufacturer Part Number: CBR04C120F5GAC; Part Number: CBR04C120F5GAC; TOLERANCE: 1%; VOLTAGE: 50V
C741 = CAP_CER_0.1UF_10V_10%_X5R_0402: CAP CER 2.2UF 10V X5R 0402; MATERIAL: X7R; Manufacturer: TDK; Manufacturer Part Number: C1005X5R1A225K050BC; PART_NUMBER: 0.1UF; Part Number: CL10B225KQ8NNNC; TOLERANCE: 10%; VOLTAGE: 10V
D19 D21 = DIODE_SCHOTTKY_30V_0.2A_SOD523: Manufacturer Part Number: PMEG3002AEB,115
D37 = LED_wp117: LED GREEN DIFFUSED 0603 SMD; Manufacturer: Lumex; Manufacturer Part Number: SML-LX0603GW-TR; Part Number: LTST-C190KGKT
FB11 FB13-FB19 = FB_0: FERRITE CHIP 120 OHM 2000MA 0603; Current: 2A; Manufacturer: Murata Electronics North America; Manufacturer Part Number: BLM18PG121SN1D; Part Number: BLM18PG121SN1D
R563 = 100K-1_16W-5%-0603_0: RES SMD 2K OHM 5% 1/10W 0402; Manufacturer: Panasonic; Manufacturer Part Number: ERJ-2GEJ202X; Part Number: ERJ-2RKF2001X; TOLERANCE: ?%; Wattage: 1/10W
R567 = RES_1.0_OHM_1_16W_0402_SMD: RES SMD 50 OHM 1% 1/16W 0402; MATERIAL: ?; Manufacturer: Yageo; Manufacturer Part Number: RC0402FR-0750RL; Part Number: RC0402FR-0751RL; TOLERANCE: 1%; Wattage: 1/16W
R568 R570 = RES_1.0_OHM_1_16W_0402_SMD: RES SMD 10 OHM 1% 1/10W 0402; MATERIAL: ?; Manufacturer: Panasonic Electronic Components; Part Number: ERJ-2RKF10R0X; TOLERANCE: 1%; Wattage: 1/10W
R569 = RES_0.9_OHM_1_10W_1%_0402_SMD: RES SMD 0.002 OHM 1% 2W 2512; Manufacturer: Stackpole Electronics Inc; Manufacturer Part Number: CSNL2512FT2L00; Part Number: CSNL2512FT2L00; TOLERANCE: 1%; WATTAGE: 2W
R889 R901 R903 = RESISTOR_1: RES SMD 200 OHM 1% 1/16W 0402; Manufacturer: VISHAY DALE; Manufacturer Part Number: CRCW0402200RFKED; Tolerance: 1%; Wattage: 1/16W
R938 R941 R943 R944 = RES_0: RES SMD 0.0OHM JUMPER 1/16W 0402; Assembly Option: LOAD; Manex: 101-0000554; Manufacturer: VISHAY DALE; Manufacturer Part Number: CRCW04020000Z0ED; Operating Temperature Maximum: -55C - 155C; Operating Temperature Minimum: -55C - 155C; PART_NUMBER: PAC_RES_02050; Package Size: 0402; Rated Power: 1/10W; Temperature Coefficient: 100ppm/C; Datasheet: http://industrial.panasonic.com/www-cgi/jvcr13pz.cgi?E+PZ+3+AOA0002+ERJ2RKF1002X+7+WW
U57 = TM4C1294NCPDT-128-TQFP_12: IC MCU 32BIT 1024KB FLASH 128TQF; Manufacturer: Texas Instruments; Manufacturer Part Number: TM4C1294NCPDTT3; Part Number: TM4C1294NCPDTT3
U58 = INA226_6: IC MONITOR PWR/CURR BIDIR 10MSOP; Manufacturer: Texas Instruments; Manufacturer Part Number: INA226AIDGSR; Part Number: INA226AIDGSR
U98 = 74LVC1G08SE-7: IC GATE AND 1CH 2-INP SOT-353; Manufacturer: Diodes
U99 = SN74AUP1T158: IC BUFF/MUX SCHMITT-TRIG SC70-6; Manufacturer: TI; Manufacturer Part Numbe: SN74AUP1T158DCKR
X4 = XTAL_4P_4: CRYSTAL 25.0000MHZ 6PF SMD; Manufacturer: EPSON; Manufacturer Part Number: FA-128 25.0MHZ6PF30PPM; Part Number: FA-128 25.0MHZ6PF30PPM
X5 = XTAL_4P_5: CRYSTAL 32.7680KHZ 12.5PF SMD; Manufacturer: EPSON; Manufacturer Part Number: FC-12M 32.7680KA-A5; Part Number: FC-12M 32.7680KA-A5
D44 D45 = LED_wp117: LED RED DIFFUSED 0603 SMD; Manufacturer: Lumex; Manufacturer Part Number: SML-LX0603IW-TR; Part Number: LTST-C190KRKT
D46 = DIODE_TVS_BI-DIR: Manufacturer: littefuse
D47 = DIODE_TVS_BI-DIR
FB12 = FB_1: FERRITE CHIP 120 OHM 2000MA 0603; Current: 2A; Manufacturer: Murata Electronics North America; Manufacturer Part Number: BLM18PG121SN1D; Part Number: BLM18PG121SN1D
J20 = eJTAG_Header_6: CONN HDR 1.27MM SMD AU 20POS; Manufacturer: Harwin Inc
J21 = 6_pin_Conn_2: CONN HEADER PH TOP 5POS 2MM SMD; Manufacturer: JST Sales America Inc; Manufacturer Part Number: B5B-PH-SM4-TB(LF)(SN); Part Number: B5B-PH-SM4-TB(LF)(SN)
J26 = 3_PIN_HEADER: CONN HEADR BRKWAY .100 3POS STR; Manufacturer: TE Connectivity; Manufacturer Part Number: 5-146280-3
J32 = B2B: CONN HEADER 2POS 2MM STR; Manufacturer: JST; Manufacturer Part Number: B2B-PH-KS-LF-SN; Part Number: B2B-PH-K-S-LF-SN
Q17-Q19 = MOSFET_N_GDS: MOSFET N-CH 30V 300MA UMT3; Manufacturer: Rohm; Manufacturer Part Number: RJU003N03T106; PART_NUMBER: RJU003N03T106
R579 R584 R589 R592 R593 R622 R925-R927 = RES_1.0_OHM_1_16W_0402_SMD: RES SMD 0.0OHM JUMPER 1/16W 0402; MATERIAL: ?; Manufacturer: VISHAY DALE; Manufacturer Part Number: CRCW04020000Z0ED; No_Mount: NM; Part Number: ERJ-2GE0R00X; TOLERANCE: ?; Wattage: 1/10W
R594 = 100K-1_16W-5%-0603_0: RES 100K OHM 1/10W 5% 0402 SMD; Manufacturer: VISHAY DALE; Manufacturer Part Number: CRCW0402100KJNED; Part Number: ERJ-2GEJ104X; TOLERANCE: 5%; Wattage: 1/10W
R900 R902 = R: RES 10 OHM 1/10W 1% 0402 SMD; MFG: Panasonic; MFG_PN: ERJ-2RKF10R0X; Manufacturer: Panasonic; Manufacturer Part Number: ERJ-2RKF10R0X; PART_NUMBER: ERJ-2RKF10R0X; Tolerance: 1%
R904-R906 = RESISTOR_1: RES SMD 10K OHM 5% 1/16W 0402; Manufacturer: VISHAY DALE; Manufacturer Part Number: CRCW040210K0JNED; Tolerance: ?%; Wattage: 1/16W
U59-U62 = TMP_152748: Part Number: IP4264CZ8-20-TTL,1
U63 = TMP_3: FILTER RC(PI) 40 OHM/12PF SMD
C764 = CAP_CER_0.1UF_10V_10%_X5R_0402: CAP CER 2200PF 50V X7R 0402; MATERIAL: X7R; Manufacturer: AVX Corporation; Manufacturer Part Number: 04025C222KAT2A; PART_NUMBER: 0.1UF; Part Number: 04025C222KAT2A; TOLERANCE: 10%; VOLTAGE: 50V
R595 = R_1: RES SMD 1K OHM 5% 1/16W 0402; Manufacturer: VISHAY DALE; Manufacturer Part Number: CRCW04021K00JNED; Part Number: ERJ-2GEJ102X; TOLERANCE: 5%; WATTAGE: 1/10W
R599 = RES_22_OHM_1_10W_5%_0402_SMD_0: RES SMD 121 OHM 1% 1/16W 0402; Manufacturer: Yageo; Manufacturer Part Number: RC0402FR-07121RL; Part Number: RC0402FR-07121RL; TOLERANCE: 1%; WATTAGE: 1/10W
R601 = RES_22_OHM_1_10W_5%_0402_SMD_0: RES SMD 0.0OHM JUMPER 1/16W 0402; Manufacturer: VISHAY DALE; Manufacturer Part Number: CRCW04020000Z0ED; Part Number: ERJ-2GE0R00X; TOLERANCE: 1%; WATTAGE: 1/10W
R602 = R_1: RES SMD 100K OHM 1% 1/16W 0402; Manufacturer: VISHAY DALE; Manufacturer Part Number: CRCW0402100KFKED; Part Number: RC0402FR-07100KL; TOLERANCE: 1%; WATTAGE: 1/16w
R603 R612 = RES_22_OHM_1_10W_5%_0402_SMD_0: RES SMD 121 OHM 1% 1/16W 0402; Manufacturer: Yageo; Manufacturer Part Number: RC0402FR-07121RL; Part Number: RC0402FR-07121RL; TOLERANCE: 1%; WATTAGE: 1/16W
R604 R605 R613 R614 = RES_1.0_OHM_1_16W_0402_SMD: RES SMD 121 OHM 1% 1/16W 0402; MATERIAL: ?; Manufacturer: Yageo; Manufacturer Part Number: RC0402FR-07121RL; Part Number: RC0402FR-07121RL; TOLERANCE: 1%; Wattage: 1/16W
R606 R615 R620 = RES_1.0_OHM_1_16W_0402_SMD: RES SMD 121 OHM 1% 1/16W 0402; MATERIAL: ?; Manufacturer: Yageo; Manufacturer Part Number: RC0402FR-07121RL; Part Number: RC0402FR-07121RL; TOLERANCE: 1%; Wattage: 1/10W
S2 = SWITCH_1: SWITCH TACTILE SPST-NO 0.05A 12V; Manufacturer: Omron Electronics Inc-EMC Div; Manufacturer Part Number: B3SL-1022P; Part Number: B3SL-1022P
U64 U67 = SN74LVC126A_1: IC QUAD 2-IN AND GATE 14-TSSOP; Manufacturer: Texas Instruments; Manufacturer Part Number: SN74LV08APWR; Part Number: SN74LV08APWR
U65 = ADM6316_0: WATCH DOG TIMER; MANUFACTURER: ANALOG DEVICES
U66 = BUF42XX_2: IC DETECTOR VOLT 2.9V CMOS 5SSOP; Manufacturer: ROhm
U68 = AT45DB641E-SHN-T: 64-Mbit DataFlash; Manufacturer: Adesto Technologies
U69 = SN74LVC1G08DCKR_0: IC GATE AND 1CH 2-INP SC-70-5; Manufacturer: Texas Instruments; Manufacturer Part Number: SN74LVC1G08DCKR; Part Number: SN74LVC1G08DCKR
C769 C770 = CAP_NONPOL: CAP CER 0.1UF 25V 10% X7R 0402; MFG: Murata; MFG_PN: GRM155R71C104KA88D; Manufacturer: MURATA; Manufacturer Part Number: GRM155R71C104KA88D; Tolerance: ±10%; Voltage: 25V
R623-R638 = RESISTOR_1: RES SMD 10K OHM 5% 1/16W 0402; Manufacturer: VISHAY DALE; Manufacturer Part Number: CRCW040210K0JNED; Tolerance: ±5%; Wattage: 1/16W
U70 U71 = CAT24C256WI-GT3: Manufacturer: ON Semiconductor
C776 = CAP_CER_0.1UF_10V_10%_X5R_0402: CAP CER 10000PF 50V X7R 0402; MATERIAL: X7R; Manufacturer: Murata Electronics North America; PART_NUMBER: 0.1UF; Part Number: GRM155R71H103KA88D; TOLERANCE: 10%; VOLTAGE: 50V
J22 = HDAF-11-18-S-13-2: 2.0x1.2mm HD Mezz Rugged, High-Density Open-Pin-Field Array Socket; Manufacturer: SAMTEC

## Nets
GND: BT2.2(-) C4P1.1 C4P2.2 C721.2(GND) C722.2(GND) C723.2(B[0]) C724.2(B[0]) C725.2(B[0]) C726.2(B[0]) C727.2(B[0]) C728.2(B[0]) C729.2(B[0]) C730.2(B[0]) C731.2(B[0]) C732.2(B[0]) C733.2(B[0]) C734.2(B[0]) C735.2(B[0]) C736.2(B[0]) C737.2(B[0]) C738.2(B[0]) C739.2(B[0]) C740.2(B[0]) C741.2(B[0]) C742.2(B[0]) C743.2(B[0]) C744.2(B[0]) C745.2(B[0]) C746.2(B[0]) C747.2(B[0]) C748.2(B[0]) C749.2(B[0]) C750.1(A[0]) C752.2(B[0]) C753.2(B[0]) C759.2(B[0]) C760.2(B[0]) C761.2(B[0]) C762.2(B[0]) C763.2(B[0]) C764.2(B[0]) C765.2(B[0]) C766.2(B[0]) C767.2(B[0]) C768.2(B[0]) C769.2 C770.2 C771.2(B[0]) C772.2(B[0]) C773.2(B[0]) C774.2(B[0]) C775.2(B[0]) C776.1(A[0]) C777.2(B[0]) C778.2(B[0]) C916.1(A[0]) C917.2(B[0]) D37.K D46.1 D47.1 J20.3 J20.5 J20.9 J20.11 J20.13 J20.15 J20.17 J20.19 J21.2 J21.SH1 J21.SH2 J22.A1 J22.A3 J22.A5 J22.A7 J22.A9 J22.B2 J22.B4 J22.B6 J22.B8 J22.B10 J22.C2 J22.C4 J22.C6 J22.C8 J22.C10 J22.D1 J22.D2 J22.D3 J22.D4 J22.D5 J22.D6 J22.D7 J22.D8 J22.D9 J22.D10 J22.D11 J22.E2 J22.E4 J22.E6 J22.E8 J22.F2 J22.F4 J22.F6 J22.F8 J22.F11 J22.G1 J22.G2 J22.G3 J22.G4 J22.G5 J22.G6 J22.G7 J22.G8 J22.G9 J22.I1 J22.I2 J22.K4 J22.K6 J22.K8 J22.L3 J22.L5 J22.L7 J22.L9 J22.L10 J22.M3 J22.M5 J22.M7 J22.M9 J26.3 J29.2 Q17.S Q18.S Q19.S R502.1 R504.1 R562.1 R572.2 R602.2(B[0]) R607.1 R608.1 R610.1 R621.1 R627.1 R628.1 R629.1 R630.1 R635.1 R636.1 R637.1 R638.1 R639.1 R640.1 R641.1 R642.1 R643.1 R905.2 R940.1 R946.2 S2.1 S2.2 U57.10(GNDA) U57.17(GND) U57.48(GND1) U57.80(GND2) U57.114(GND3) U58.7(GND) U59.9 U60.9 U61.9 U62.9 U63.9 U64.7(GND) U65.2(GND) U66.3(GND) U67.7(GND) U68.7(GND) U69.3(GND) U70.4(VSS) U71.4(VSS) U98.3(GND) U99.2(GND) U99.4(C) X4.2 X4.4 ; also on sheet 1 2 10 11 12 13 14 15 16 17 18 19 20 21 22 23 24 25 26 27 28 29 30 31 32 33 34 35 36 43 44 45 46 47 48 49 50 51 52 53 54
V2_BACK_ON: R507.1(A[0]) ; also on sheet 28
V3P3_TIVA: C721.1(IN) C722.1(IN) C760.1(A[0]) C761.1(A[0]) C763.1(A[0]) C766.1(A[0]) C767.1(A[0]) C769.1 C770.1 C916.2(B[0]) C917.1(A[0]) D22.K FB11.2 J29.1 R480.2 R490.2 R528.2 R547.2 R548.2 R549.2 R550.2 R551.2 R552.2 R553.2 R554.2 R555.2 R556.2 R557.2 R558.2 R559.2 R560.2 R561.2 R566.2 R569.2(B[0]) R570.2(B[0]) R573.2 R595.1(A[0]) R596.2 R597.2 R598.2 R600.2 R616.2 R617.2 R618.2 R623.2 R624.2 R625.2 R626.2 R631.2 R632.2 R633.2 R634.2 R770.2 R889.2 R920.2 R921.2 R938.2 R945.2 U58.8(VBUS) U64.14(VCC) U65.5(VCC) U66.2(VDD) U68.6(VCC) U69.5(VCC) U70.8(VCC) U71.8(VCC) U98.5(VCC) U99.5(VCC) ; also on sheet 46 48
V3P3_TIVA_CM: C750.2(B[0]) R568.2(B[0]) R569.1(A[0]) R571.1 U58.6(VS) ; also on sheet 2
V3P3_TIVA_FIL: C721.3(OUT) C723.1(A[0]) C727.1(A[0]) C728.1(A[0]) C729.1(A[0]) C730.1(A[0]) C731.1(A[0]) C732.1(A[0]) C733.1(A[0]) C734.1(A[0]) C735.1(A[0]) C742.1(A[0]) C743.1(A[0]) C744.1(A[0]) C745.1(A[0]) C746.1(A[0]) C747.1(A[0]) U57.7(VDD) U57.16(VDD1) U57.26(VDD2) U57.28(VDD3) U57.39(VDD4) U57.47(VDD5) U57.69(VDD6) U57.79(VDD7) U57.90(VDD8) U57.101(VDD9) U57.113(VDD10) U57.122(VDD11) ; also on sheet 36
V3P3_TIVA_LT: C753.1(A[0]) C765.1(A[0]) FB12.1 FB16.1 J20.1 R546.2 R594.2(B[0]) R611.2 R901.2 R903.2 R942.2 U67.14(VCC) ; also on sheet 1 2 19 20 21 28 29 31 43 44 46 47 52 54
V3P3_TIVA_RTC: C726.1(A[0]) C752.1(A[0]) R567.1(A[0]) U57.68(VBAT)
V3P3_TRXFE: FB15.2 FB18.1 ; also on sheet 47
V5_USB_TIVA: C4P2.1 D19.K U57.96(PB1/USB0VBUS)
V5P0: C4P1.2 D19.A ; also on sheet 18 25 29 30 31 33 49
V12P0_TIVA: J32.1 R904.1 ; also on sheet 29
VDDC: C738.1(A[0]) C739.1(A[0]) C740.1(A[0]) C741.1(A[0]) U57.87(VDDC) U57.115(VDDC1)
2G_SIM_PRESENCE: J22.A2 ; also on sheet 1
2GMODULE_POWEROFF: J22.H9 ; also on sheet 1
A_TIVA_JTAG_RESET: R605.2(B[0]) R608.2 U64.12(4A)
A_TIVA_RESET: R620.2(B[0]) R621.2 R622.2(B[0]) U64.13(4B)
AND_A: R943.1 U98.1(A)
AND_B: R944.1 U98.2(B)
B_TIVA_RESET: R597.1 R606.2(B[0]) R607.2 U64.4(2A)
BB_ETH_MDI_N0: J22.C1 ; also on sheet 23
BB_ETH_MDI_N1: J22.C3 ; also on sheet 23
BB_ETH_MDI_N2: J22.C5 ; also on sheet 23
BB_ETH_MDI_N3: J22.C7 ; also on sheet 23
BB_ETH_MDI_P0: J22.B1 ; also on sheet 23
BB_ETH_MDI_P1: J22.B3 ; also on sheet 23
BB_ETH_MDI_P2: J22.B5 ; also on sheet 23
BB_ETH_MDI_P3: J22.B7 ; also on sheet 23
BB_SENSOR_ALERT: J22.H1 R533.1(A[0])
BUZZER_ON: R906.1 U57.3(PD2/AIN13)
C_TIVA_JTAG_TDO: R925.2(B[0]) R927.2(B[0]) U59.1
CFG_IOEXP_TIVA_INT: U57.116(PJ0) ; also on sheet 1
ETHSW_INT_TIVA: U57.107(PN0) ; also on sheet 19
ETHSW_RESETN: R612.2(B[0]) ; also on sheet 19
FE_12V_CTRL: C776.2(B[0]) J22.H8 R502.2 U57.14(PE1/AIN2)
FE_RESET_OUT: J22.J9 R614.2(B[0]) R642.2
ICD_RESET: R770.1 U64.9(3A)
IOEXP_ID_EEPROM_WP: R631.1 R638.2 U71.7(WP) ; also on sheet 1
IOEXP_INVEN_EEPROM_WP: R623.1 R630.2 U70.7(WP) ; also on sheet 1
IOEXP_TIVA_INT: U57.15(PE0/AIN3) ; also on sheet 1
ISO_SOC_TRXFE_GPIO1: J22.L1 ; also on sheet 47
ISO_SOC_TRXFE_GPIO2: J22.L2 ; also on sheet 47
ISO_SOC_TRXFE_GPIO3: J22.M1 ; also on sheet 47
ISO_SOC_TRXFE_GPIO4: J22.M2 ; also on sheet 47
ISO_SOC_TRXFE_GPIO5: J22.B11 ; also on sheet 47
ISO_SOC_TRXFE_GPIO6: J22.C11 ; also on sheet 47
ISO_TIVA_TRXFECONN_GPIO1: J22.J1 ; also on sheet 47
ISO_TIVA_TRXFECONN_GPIO2: J22.J2 ; also on sheet 47
ISO_TIVA_TRXFECONN_GPIO3: J22.K1 ; also on sheet 47
L_TIVA_TRXFECONN_I2C2_SCLK: J22.E7 ; also on sheet 47
L_TIVA_TRXFECONN_I2C2_SDA: J22.F7 ; also on sheet 47
L_TIVA_WAKEn: R940.2 R941.1 U98.4(Y)
L_TRXFE_RESET: J22.E10 ; also on sheet 47
LED_TIVA_GPIO: R594.1(A[0]) U57.77(PM1) U63.3
LIGHT_SENSE_INT: R500.2(B[0]) ; also on sheet 46
MSATA0_TIVA_DAS: U57.6(PQ1) ; also on sheet 43
MSATA1_TIVA_DAS: U57.83(PL2) ; also on sheet 44
MSATA_PWR_EN: U57.30(PH1) ; also on sheet 43
OCT_12V_ONOFF: R517.2(B[0]) ; also on sheet 28
OCT_DC_OK: R913.2(B[0]) ; also on sheet 12 32
OCT_PWR_ALRT: R520.1(A[0]) ; also on sheet 28
OCT_THERMAL_TRIP_L: R506.1(A[0]) ; also on sheet 12
OCT_TIVA_JTAG_TDO: R927.1(A[0]) ; also on sheet 12
OCT_USB1_DM: J22.F5 ; also on sheet 53
OCT_USB1_DP: J22.E5 ; also on sheet 53
OCT_USB1_SSRX_N: J22.F1 ; also on sheet 53
OCT_USB1_SSRX_P: J22.E1 ; also on sheet 53
OCT_USB1_SSTX_N: J22.F3 ; also on sheet 53
OCT_USB1_SSTX_P: J22.E3 ; also on sheet 53
PCIE0_GBC_CLKN: J22.M8 ; also on sheet 35
PCIE0_GBC_CLKP: J22.L8 ; also on sheet 35
PCIE0_RXN: J22.M6 ; also on sheet 50
PCIE0_RXP: J22.L6 ; also on sheet 50
PCIE0_TXN: J22.M4 ; also on sheet 50
PCIE0_TXP: J22.L4 ; also on sheet 50
PW_EXIST: R942.1 U99.3(B)
R_IRQ_INTRPT: J22.J4 R641.2 ; also on sheet 1
R_WD_INPUT: R601.2(B[0]) U65.4(WDI)
R_WD_TIVA_RST: R599.1(A[0]) R602.1(A[0]) U65.1(NRESET)
SATA_PWR_ALERT: U57.11(PQ2) ; also on sheet 43
SUPR_TIVA_RESET: R609.2(B[0]) R610.2 R622.1(A[0]) U69.2(B)
SYNC_RESET: J22.J5 R613.2(B[0])
SYNC_TIVA_INT: J22.E11 R480.1 R505.2(B[0])
SYNCCONN_TIVA_UART_RX: J22.K3 R503.1(A[0]) R643.2
THERM_ALERT: J22.H7 ; also on sheet 31
TIVA_2GMODULE_PWR_ON: J22.I3 R640.2 ; also on sheet 1
TIVA_DEBUG: JP1.2 R562.2 U57.106(PP5)
TIVA_DEBUG_RX: R487.1(A[0]) R581.1(A[0])
TIVA_DEBUG_TX: R481.1(A[0]) R580.1(A[0])
TIVA_ETHSW_RESET: R534.2(B[0]) R611.1 U67.2(1B)
TIVA_FE_RESET_OUT: R531.2(B[0]) U67.10(3B)
TIVA_FLASH_CLK: R493.2(B[0]) U68.2(SCK)
TIVA_FLASH_MISO: R516.1(A[0]) U68.8(SO)
TIVA_FLASH_MOSI: R515.1(A[0]) U68.1(SI)
TIVA_FLASH_nCS: R492.2(B[0]) R617.1 U68.4(nCS)
TIVA_GPIO_PH0: J29.4 U57.29(PH0)
TIVA_GPIO_PL5: R527.1(A[0]) ; also on sheet 21
TIVA_GPIO_PM6: U57.72(PM6) ; also on sheet 21
TIVA_I2C0_SCLK: J29.5 R489.2(B[0]) R556.1 ; also on sheet 19 52
TIVA_I2C0_SDA: J29.6 R483.2(B[0]) R557.1 ; also on sheet 19 52
TIVA_I2C3_SCLK: J22.E9 R522.2(B[0]) R553.1
TIVA_I2C3_SDA: J22.F9 R524.2(B[0]) R552.1
TIVA_I2C7_SCL: R496.2(B[0]) R921.1 U63.2
TIVA_I2C7_SDA: R497.2(B[0]) R920.1 U63.1
TIVA_JTAG_RESET: R573.1 U60.2 U64.10(3B) ; also on sheet 12
TIVA_JTAG_TCK: R498.1(A[0]) U59.2 ; also on sheet 12
TIVA_JTAG_TDI: R501.1(A[0]) U60.3
TIVA_JTAG_TDO: R485.1(A[0]) R925.1(A[0]) R926.1(A[0])
TIVA_JTAG_TMS: R499.1(A[0]) U59.3 ; also on sheet 12
TIVA_JTAG_TRCLK: R511.2(B[0]) R579.1(A[0])
TIVA_JTAG_TRD0: R510.2(B[0]) R584.1(A[0])
TIVA_JTAG_TRD1: R509.2(B[0]) R589.1(A[0])
TIVA_JTAG_TRD2: R508.2(B[0]) R592.1(A[0])
TIVA_JTAG_TRD3: R513.2(B[0]) R593.1(A[0])
TIVA_MODULE_UART1_RIN: J22.A4 R528.1 U57.112(PN5)
TIVA_OCT_GPIO1: R512.1(A[0]) ; also on sheet 10
TIVA_OCT_GPIO2: R514.1(A[0]) ; also on sheet 10
TIVA_OCT_GPIO3: U57.84(PL3) ; also on sheet 10
TIVA_OCT_GPIO4: U57.85(PL4) ; also on sheet 10
TIVA_OCT_JTAG_TDI: R926.2(B[0]) ; also on sheet 12
TIVA_OCT_RESETn: D21.A R600.1 ; also on sheet 32
TIVA_OCT_UART3_RX: R491.1(A[0]) ; also on sheet 25
TIVA_OCT_UART3_TX: R484.1(A[0]) ; also on sheet 25
TIVA_PSE_I2C8_SCLK: J22.K9 R488.1(A[0]) R560.1 U70.6(SCL) U71.6(SCL) ; also on sheet 46
TIVA_PSE_I2C8_SDA: J22.K7 R482.1(A[0]) R561.1 U70.5(SDA) U71.5(SDA) ; also on sheet 46
TIVA_PWR_ALRT: R566.1 U57.32(PH3) U58.3(ALERT) ; also on sheet 29
TIVA_PWRMNTR_I2C6_SCLK: R494.1(A[0]) R555.1 U58.5(SCL) ; also on sheet 1 28 29 31 43
TIVA_PWRMNTR_I2C6_SDA: R495.1(A[0]) R554.1 U58.4(SDA) ; also on sheet 1 28 29 31 43
TIVA_RESET: R604.2(B[0]) R619.1(A[0]) U57.70(~{RST}) U64.2(1B) U67.1(1A) U67.4(2A) U67.9(3A) U67.12(4A) U68.3(nRST) ; also on sheet 1 48
TIVA_RESET_TO_PROC: R544.1(A[0]) R598.1 U64.1(1A)
TIVA_SYNC_RESET: R545.1(A[0]) U67.5(2B)
TIVA_SYNCCONN_GPIO1: J22.I4 R639.2 ; also on sheet 1
TIVA_SYNCCONN_UART_TX: J22.K5 R486.1(A[0])
TIVA_TEMPSEN_I2C1_SCLK: R518.1(A[0]) R558.1 ; also on sheet 46
TIVA_TEMPSEN_I2C1_SDA: R519.1(A[0]) R559.1 ; also on sheet 46
TIVA_TRXFE_RESET: R543.2(B[0]) U67.13(4B)
TIVA_TRXFECONN_GPIO1: R535.1(A[0]) ; also on sheet 47
TIVA_TRXFECONN_GPIO2: R536.1(A[0]) ; also on sheet 47
TIVA_TRXFECONN_GPIO3: R538.1(A[0]) ; also on sheet 47
TIVA_TRXFECONN_I2C2_SCLK: R523.1(A[0]) R549.1 ; also on sheet 47 48
TIVA_TRXFECONN_I2C2_SDA: R521.1(A[0]) R548.1 ; also on sheet 47 48
TIVA_TRXFECONN_I2C4_SCLK: J22.B9 R525.2(B[0]) R551.1
TIVA_TRXFECONN_I2C4_SDA: J22.C9 R526.2(B[0]) R550.1
TIVA_TRXFECONN_RESET: D18.A R541.1(A[0]) R546.1
TIVA_UART4_CTS: J22.A11 U57.21(PK3/AIN19)
TIVA_UART4_RTS: J22.A8 U57.20(PK2/AIN18)
TIVA_UART4_RXD: J22.A6 U57.18(PK0/AIN16)
TIVA_UART4_TXD: J22.A10 U57.19(PK1/AIN17)
TIVA_UART6_RX: R539.2(B[0]) ; also on sheet 21
TIVA_UART6_TX: R540.2(B[0]) ; also on sheet 21
TIVA_USB0_DM: R530.1(A[0]) ; also on sheet 22
TIVA_USB0_DP: R529.1(A[0]) ; also on sheet 22
TIVA_USB_ID: R490.1 R504.2 U57.95(PB0/USB0ID)
TIVA_USER_LED1: R900.1 ; also on sheet 1
TIVA_USER_LED2: R902.1 ; also on sheet 1
TIVA_WAKEn: R941.2 U57.64(~{WAKE})
TPM_I2C_MUX_SEL: U57.78(PM0) ; also on sheet 48
TPM_INT_REQ: U57.127(PD6/AIN5) ; also on sheet 48
TRXFE_12V_ONOFF: R542.2(B[0]) ; also on sheet 31 47
TRXFE_DET: J22.I5 R939.2(B[0]) R944.2 R945.1 R946.1
TRXFE_IN_12V: FB13.2 FB14.2 FB17.2 FB19.1 ; also on sheet 31
TRXFE_RESET: R615.2(B[0]) ; also on sheet 47
TRXFE_SENSOR_ALERT: J22.H2 R532.2(B[0])
TRXFECONN_RESET: D18.K J22.K2
UART_SEL: R914.2(B[0]) ; also on sheet 10 25
VRM_ALERT#: U57.75(PM3) ; also on sheet 52
WD_INPUT: R537.2(B[0]) R601.1(A[0])
WD_TIVA_RST: R596.1 R599.2(B[0]) U64.5(2B)
N305820: C736.1(A[0]) U57.88(OSC0) X4.3
N305856: C737.1(A[0]) R563.2(B[0]) X4.1
N305944: R565.2(B[0]) U57.66(XOSC0)
N305998: C748.1(A[0]) R564.1(A[0]) X5.2
N306002: C749.1(A[0]) R565.1(A[0]) X5.1
N306032: R564.2(B[0]) U57.67(XOSC1)
N306040: C724.1(A[0]) C725.1(A[0]) FB11.1 U57.9(VREFA+)
N307638: C722.3(OUT) U57.8(VDDA)
N307654: R563.1(A[0]) U57.89(OSC1)
N307806: BT2.1(+) R567.2(B[0])
N313547: R535.2(B[0]) U57.109(PN2)
N313551: R536.2(B[0]) U57.110(PN3)
N313627: R505.1(A[0]) U57.128(PD7/AIN4)
N313679: R538.2(B[0]) U57.111(PN4)
N313861: R487.2(B[0]) U57.33(PA0/U0RX)
N313865: R481.2(B[0]) U57.34(PA1/U0TX)
N314353: R542.1(A[0]) U57.103(PP2)
N314363: R531.1(A[0]) U57.76(PM2)
N314497: R488.2(B[0]) U57.35(PA2/SSI0CLK)
N314501: R482.2(B[0]) U57.36(PA3/SSI0FSS)
N314667: R496.1(A[0]) U57.1(PD0/AIN15)
N314857: R503.2(B[0]) U57.25(PC4/C1-)
N314903: R486.2(B[0]) U57.24(PC5/C1+)
N314937: R543.1(A[0]) U57.105(PP4)
N314991: R527.2(B[0]) U57.86(PL5)
N315033: R520.2(B[0]) U57.117(PJ1)
N315269: R498.2(B[0]) U57.100(PC0/TCK/SWCLK)
N315273: R499.2(B[0]) U57.99(PC1/TMS/SWDIO)
N315277: R501.2(B[0]) U57.98(PC2/TDI)
N315287: R485.2(B[0]) U57.97(PC3/TDO/SWO)
N315415: R544.2(B[0]) U57.27(PQ3)
N315471: R545.2(B[0]) U57.102(PQ4)
N315497: R541.2(B[0]) U57.5(PQ0)
N315619: R506.2(B[0]) U57.23(PC6/C0+)
N315623: R507.2(B[0]) U57.22(PC7/C0-)
N315783: R494.2(B[0]) U57.40(PA6)
N315787: R495.2(B[0]) U57.41(PA7)
N316005: R518.2(B[0]) U57.49(PG0)
N316009: R519.2(B[0]) U57.50(PG1)
N316121: R489.1(A[0]) U57.91(PB2/I2C0SCL)
N316125: R483.1(A[0]) U57.92(PB3/I2C0SDA)
N316321: R530.2(B[0]) U57.93(PL7/USB0DM)
N316325: R529.2(B[0]) U57.94(PL6/USB0DP)
N316341: R497.1(A[0]) U57.2(PD1/AIN14)
N316399: R522.1(A[0]) U57.63(PK4)
N316433: R524.1(A[0]) U57.62(PK5)
N316461: R525.1(A[0]) U57.61(PK6)
N316495: R526.1(A[0]) U57.60(PK7)
N316559: R521.2(B[0]) U57.81(PL0)
N316563: R523.2(B[0]) U57.82(PL1)
N358452: C775.1(A[0]) FB17.1 J22.H10 J22.H11
N358496: C772.1(A[0]) FB15.1 J22.I6 J22.I7 J22.I8
N358586: C777.1(A[0]) FB14.1 J22.I10 J22.I11
N358626: C773.1(A[0]) FB18.2 J22.J6 J22.J7 J22.J8
N358700: C774.1(A[0]) FB13.1 J22.J10 J22.J11
N358786: C778.1(A[0]) FB19.2 J22.K10 J22.K11
N19674436: R534.1(A[0]) U57.73(PM5)
N19700917: R500.1(A[0]) U57.4(PD3/AIN12)
N19700991: R539.1(A[0]) U57.118(PP0/C2+)
N19700993: R540.1(A[0]) U57.119(PP1/C2-)
N19701060: R537.1(A[0]) U57.71(PM7)
N19701162: R508.1(A[0]) U57.42(PF0)
N19701296: R509.1(A[0]) U57.43(PF1)
N19701306: R510.1(A[0]) U57.44(PF2)
N19701308: R511.1(A[0]) U57.45(PF3)
N19701317: R513.1(A[0]) U57.46(PF4)
N19703020: R491.2(B[0]) U57.37(PA4/SSI0XDAT0)
N19703023: R484.2(B[0]) U57.38(PA5/SSI0XDAT1)
N19716571: R512.2(B[0]) U57.13(PE2/AIN1)
N19716578: R514.2(B[0]) U57.12(PE3/AIN0)
N19765493: R517.1(A[0]) U57.31(PH2)
N20576884: R515.2(B[0]) U57.123(PE4/AIN9)
N20576887: R516.2(B[0]) U57.124(PE5/AIN8)
N20781285: J20.2 U59.6
N20781290: J20.4 U59.7
N20781299: J20.6 U59.8
N21104531: J20.8 U60.6
N21104610: J20.10 U60.7
N21104687: R584.2(B[0]) U61.2
N21104736: J20.14 U61.7
N21104983: R589.2(B[0]) U61.1
N21105007: J20.16 U61.8
N21105045: R579.2(B[0]) U60.1
N21105084: J20.12 U60.8
N21105133: R592.2(B[0]) U62.2
N21105138: R593.2(B[0]) U62.1
N21105177: J20.20 U62.8
N21105184: J20.18 U62.7
N24808139: C751.1(A[0]) R568.1(A[0]) U58.10(IN+)
N24808141: C751.2(B[0]) R570.1(A[0]) U58.9(IN-)
N24808193: R571.2 U58.2(A0)
N24808195: R572.1 U58.1(A1)
N25048313: JP1.1 R547.1
N25108064: C771.1(A[0]) FB16.2 J22.H3 J22.H4 J22.H5 J22.H6
N25968767: R533.2(B[0]) U57.108(PN1)
N25968814: R532.1(A[0]) U57.74(PM4)
N25969232: R492.1(A[0]) U57.121(PB4/AIN10)
N26213463: R493.1(A[0]) U57.120(PB5/AIN11)
N30535296: R616.1 R619.2(B[0]) U68.5(WP)
N30536056: C768.1(A[0]) D22.A R618.1 S2.3 S2.4 U69.1(A)
N30536074: R620.1(A[0]) U69.4(Y)
N30536663: C764.1(A[0]) U66.5(CT)
N30536673: R609.1(A[0]) U66.1(VOUT)
N31009942: C762.1(A[0]) R595.2(B[0]) U65.3(NMR)
N31036562: R603.1(A[0]) U64.3(1Y)
N31036568: R605.1(A[0]) U64.8(3Y)
N31036575: R606.1(A[0]) U64.11(4Y)
N31036588: D21.K R603.2(B[0])
N31036612: R604.1(A[0]) U64.6(2Y)
N31037211: R614.1(A[0]) U67.8(3Y)
N31037213: R612.1(A[0]) U67.3(1Y)
N31037215: R615.1(A[0]) U67.11(4Y)
N31037217: R613.1(A[0]) U67.6(2Y)
N31085804: D47.2 J26.1 R580.2(B[0])
N31085806: D46.2 J26.2 R581.2(B[0])
N31251981: C759.1(A[0]) FB12.2 J21.1
N31252008: J21.3 U63.8
N31252010: J21.4 U63.7
N31252012: J21.5 U63.6
N32035261: R624.1 R627.2 U70.1(A0)
N32035274: R625.1 R628.2 U70.2(A1)
N32035290: R626.1 R629.2 U70.3(A2)
N32035752: R632.1 R635.2 U71.1(A0)
N32035767: R633.1 R636.2 U71.2(A1)
N32035775: R634.1 R637.2 U71.3(A2)
N33535707: D44.K Q17.D
N33535710: Q17.G R900.2
N33535856: D45.K Q18.D
N33535858: Q18.G R902.2
N33536396: Q19.G R905.1 R906.2
N33536749: J32.2 Q19.D R904.2
N33641751: R913.1(A[0]) U57.104(PP3)
N33646378: R914.1(A[0]) U57.126(PD5/AIN6)
N33840429: J22.J3 R938.1
N33840496: R939.1(A[0]) U57.125(PD4/AIN7)
N33844879: R943.2 U99.6(Y)
N34189368: D44.A R901.1
N34189369: D45.A R903.1
N34189749: D37.A R889.1

Not connected (* = marked no-connect by the designer): J20 7*; J22 F10 G10* G11* I9* L11* M10* M11* SH1* SH2* SH3* SH4*; J29 3*; MH14 1*; U57 65(~{HIB})*; U59 4* 5*; U60 4* 5*; U61 3* 4* 5* 6*; U62 3* 4* 5* 6*; U63 4* 5*; U66 4(NC)*; U99 1(A)*

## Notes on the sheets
sheet 37
- 8
- 7
- 6
- 5
- 4
- 3
- 2
- 1
- UNLESS OTHERWISE SPECIFIED:
  RESISTORS ARE 0402 PACKAGE, POWER RATING < 0.5W & TOLERANCE > 1%
  CAPACITORS ARE 0402 PACKAGE & TOLERANCE OF 10%
- D
- D
- C
- C
- B
- B
- MH14 place 2inch away from J29
- 9774070243R
- A
- A
- 8
- 7
- 6
- 5
- 4
- 3
- 2
- 1
sheet 38
- UNLESS OTHERWISE SPECIFIED:
  RESISTORS ARE 0402 PACKAGE, POWER RATING < 0.5W & TOLERANCE > 1%
  CAPACITORS ARE 0402 PACKAGE & TOLERANCE OF 10%
- VDDC-OUTPUT FROM CONTROLLER
- Address:0X41
- CURRENT MONITORING FOR V3P3_TIVA
- TIVA RTC
sheet 39
- this reference GBCV1
- JTAG CHAIN:
- Place R926,R927
- remove R925
sheet 40
- watch dog
- oct_rst
- manual reset
sheet 41
- ADDRESS:0XA0
- SIZE-256KB
- INVENTORY EEPROM
- ADDRESS:0XA1
- SIZE-256KB
- EEPROM FOR STORING SERIAL ID
sheet 42
- from ethernet switch
- Layout note:
  diff 100ohm,
  length match±20mil
- USB3.0
- To 81xx gpio
- To 81xx gpio
- BB BOARD PROVIDE TO GBC
- RST ON BB_BOARD
- temp alert
- TO OCT GPIO?
- TO TIVA RX
- connec to GPS on bb board
- use iic8  to connect to syncconn board
- to 7130 qlm1 clk
